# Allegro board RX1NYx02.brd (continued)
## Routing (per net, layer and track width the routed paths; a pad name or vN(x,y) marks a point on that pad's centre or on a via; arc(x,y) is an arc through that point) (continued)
GND_BD1: length 1822.2
  TOP w0.102: v1(91.38,-57.26) 91.39,-57.27 U26.3
  TOP w0.254: C16.2 v1(93.7,-62.06) ; U24.9 v1(94.4,-67.31) ; C2.1 v1(90.66,-49.41) ; C4.1 82.16,-40.92 v1(82.39,-41.15) ; C1.2 v1(108.7,-32.26) ; C3.1 82.16,-44.1 v1(82.39,-44.33) ; C5.1 82.16,-52.1 v1(82.39,-52.33) ; C9.1 82.16,-47.27 v1(82.39,-47.5) ; C166.2 v1(94,-58.86) ; C8.1 v1(90.66,-43.06)
  TOP w0.381: v1(1.94,-42.11) v1(3.43,-42.11) ; v1(89.65,-39.63) 90.22,-39.63 90.6,-40.01 U6.3 ; v1(1.94,-32.7) v1(3.43,-32.7) ; v1(1.94,-36.3) v1(3.43,-36.3) ; P_OCP1.A46 v1(3.43,-56.62) ; v1(3.43,-62.02) P_OCP1.A55 ; P_OCP1.A52 v1(3.43,-60.22) ; v1(1.94,-47.51) v1(3.43,-47.51) ; v1(1.94,-15.1) v1(3.43,-15.1) ; U5.3 v1(87.11,-50.41) ; v1(1.94,-38.1) v1(3.43,-38.1) ; v1(91.3,-45.85) 91.3,-46.6 90.92,-46.98 U1.3 ; P_OCP1.A49 v1(3.43,-58.42) ; v1(1.94,-29.1) v1(3.43,-29.1) ; U3.3 v1(87.11,-39.23) ; v1(1.94,-30.9) v1(3.43,-30.9) ; v1(1.94,-43.91) v1(3.43,-43.91) ; U7.3 v1(87.11,-45.58) ; P_OCP1.A43 v1(3.43,-54.82) ; P_OCP1.A64 v1(3.43,-67.42) ; U4.1 v1(98.92,-32.26) ; v1(1.94,-16.9) v1(3.43,-16.9) ; P_OCP1.A58 v1(3.43,-63.82) ; U2.3 v1(87.11,-42.41) ; v1(1.94,-49.31) v1(3.43,-49.31) ; P_OCP1.A61 v1(3.43,-65.62) ; v1(1.94,-34.5) v1(3.43,-34.5) ; P_OCP1.A67 v1(3.43,-69.22) ; v1(1.94,-45.71) v1(3.43,-45.71)
  TOP w0.508: C163.1 96.17,-29.64 v1(96.89,-30.36) ; v1(104.51,-30.61) 104.44,-30.54 Q1.2 ; SW1.2 v1(91.55,-44.45) ; C148.1 v1(88.81,-63.63) ; DS_BD1_PWR.2 v1(105.65,-15.24) ; C149.1 v1(88.81,-68.2)
  GND w0.254: 19.35,-50.36 P_CPU_OCP_3_P.3 ; P_CPU_OCP_3_P.3 20.48,-50.36 ; P_CPU_OCP_3_P.3 20.48,-51.48 ; P_CPU_OCP_3_P.3 19.35,-51.48 ; 15.05,-11.86 P_BD1_CLK2_N.3 ; P_BD1_CLK2_N.3 15.05,-10.73 ; P_BD1_CLK2_N.3 16.18,-10.73 ; P_BD1_CLK2_N.3 16.18,-11.86 ; P_OCP_CPU_1_P.4 100.49,-23.29 ; P_OCP_CPU_1_P.4 99.36,-23.29 ; P_OCP_CPU_1_P.4 99.36,-22.16 ; P_OCP_CPU_1_P.4 100.49,-22.16 ; 60.77,-7.56 P_BD1_CLK3_N.4 ; P_BD1_CLK3_N.4 61.9,-6.43 ; P_BD1_CLK3_N.4 60.77,-6.43 ; P_BD1_CLK3_N.4 61.9,-7.56 ; 65.07,-74.34 P_OCP_CPU_6_P.3 ; P_OCP_CPU_6_P.3 66.2,-73.22 ; P_OCP_CPU_6_P.3 65.07,-73.22 ; P_OCP_CPU_6_P.3 66.2,-74.34 ; 83.58,-36.8 P1.2 ; P1.2 85.05,-36.8 ; P1.2 83.58,-35.34 ; P1.2 85.05,-35.34 ; P_OCP_CPU_1_P.5 97.14,-23.29 ; P_OCP_CPU_1_P.5 96.01,-23.29 ; P_OCP_CPU_1_P.5 97.14,-22.16 ; P_OCP_CPU_1_P.5 96.01,-22.16 ; 65.07,-34.63 P_OCP_CPU_3_N.4 ; P_OCP_CPU_3_N.4 66.2,-34.63 ; P_OCP_CPU_3_N.4 66.2,-35.75 ; P_OCP_CPU_3_N.4 65.07,-35.75 ; P_CPU_OCP_0_P.3 31.91,-23.2 ; P_CPU_OCP_0_P.3 30.78,-24.32 ; P_CPU_OCP_0_P.3 31.91,-24.32 ; P_CPU_OCP_0_P.3 30.78,-23.2 ; 27.43,-23.2 P_CPU_OCP_0_P.2 ; P_CPU_OCP_0_P.2 28.56,-24.32 ; P_CPU_OCP_0_P.2 27.43,-24.32 ; P_CPU_OCP_0_P.2 28.56,-23.2 ; 18.4,-28.62 P_CPU_OCP_0_N.2 ; P_CPU_OCP_0_N.2 19.53,-28.62 ; P_CPU_OCP_0_N.2 19.53,-27.5 ; P_CPU_OCP_0_N.2 18.4,-27.5 ; 65.07,-70.99 P_OCP_CPU_6_P.2 ; P_OCP_CPU_6_P.2 65.07,-69.87 ; P_OCP_CPU_6_P.2 66.2,-69.87 ; P_OCP_CPU_6_P.2 66.2,-70.99 ; P_OCP_CPU_4_N.3 50.47,-35.75 ; P_OCP_CPU_4_N.3 49.34,-35.75 ; P_OCP_CPU_4_N.3 50.47,-34.63 ; P_OCP_CPU_4_N.3 49.34,-34.63 ; 60.77,-37.98 P_OCP_CPU_3_N.2 ; P_OCP_CPU_3_N.2 61.9,-39.1 ; P_OCP_CPU_3_N.2 61.9,-37.98 ; P_OCP_CPU_3_N.2 60.77,-39.1 ; 64.12,-23.2 P_OCP_CPU_0_P.5 ; P_OCP_CPU_0_P.5 65.25,-24.32 ; P_OCP_CPU_0_P.5 65.25,-23.2 ; P_OCP_CPU_0_P.5 64.12,-24.32 ; 30.78,-51.48 P_CPU_OCP_2_P.3 ; P_CPU_OCP_2_P.3 31.91,-50.36 ; P_CPU_OCP_2_P.3 30.78,-50.36 ; P_CPU_OCP_2_P.3 31.91,-51.48 ; P_BD1_CLK1_P.2 97.14,-6.43 ; P_BD1_CLK1_P.2 96.01,-6.43 ; P_BD1_CLK1_P.2 97.14,-7.56 ; P_BD1_CLK1_P.2 96.01,-7.56 ; P_BD1_CLK0_P.2 51.42,-7.56 ; P_BD1_CLK0_P.2 50.29,-7.56 ; P_BD1_CLK0_P.2 50.29,-6.43 ; P_BD1_CLK0_P.2 51.42,-6.43 ; 60.77,-34.63 P_OCP_CPU_3_N.3 ; P_OCP_CPU_3_N.3 60.77,-35.75 ; P_OCP_CPU_3_N.3 61.9,-35.75 ; P_OCP_CPU_3_N.3 61.9,-34.63 ; P_OCP_CPU_2_P.4 73.33,-51.48 ; P_OCP_CPU_2_P.4 72.2,-50.36 ; P_OCP_CPU_2_P.4 72.2,-51.48 ; P_OCP_CPU_2_P.4 73.33,-50.36 ; P_CPU_OCP_7_N.5 20.48,-60.84 ; P_CPU_OCP_7_N.5 19.35,-60.84 ; P_CPU_OCP_7_N.5 20.48,-61.96 ; P_CPU_OCP_7_N.5 19.35,-61.96 ; 76.5,-51.48 P_OCP_CPU_2_P.3 ; P_OCP_CPU_2_P.3 76.5,-50.36 ; P_OCP_CPU_2_P.3 77.63,-50.36 ; P_OCP_CPU_2_P.3 77.63,-51.48 ; P_BD1_CMTS_N.3 97.46,-58.61 ; P_BD1_CMTS_N.3 96.33,-58.61 ; P_BD1_CMTS_N.3 97.46,-57.49 ; P_BD1_CMTS_N.3 96.33,-57.49 ; P_BD1_CLK0_N.2 42.39,-10.73 ; P_BD1_CLK0_N.2 42.39,-11.86 ; P_BD1_CLK0_N.2 41.26,-11.86 ; P_BD1_CLK0_N.2 41.26,-10.73 ; 15.05,-35.75 P_CPU_OCP_3_N.3 ; P_CPU_OCP_3_N.3 16.18,-34.63 ; P_CPU_OCP_3_N.3 15.05,-34.63 ; P_CPU_OCP_3_N.3 16.18,-35.75 ; P_CPU_OCP_1_N.2 42.39,-27.5 ; P_CPU_OCP_1_N.2 41.26,-28.62 ; P_CPU_OCP_1_N.2 42.39,-28.62 ; P_CPU_OCP_1_N.2 41.26,-27.5 ; 42.21,-73.22 P_CPU_OCP_5_P.3 ; P_CPU_OCP_5_P.3 42.21,-74.34 ; P_CPU_OCP_5_P.3 43.34,-74.34 ; P_CPU_OCP_5_P.3 43.34,-73.22 ; 37.91,-74.34 P_CPU_OCP_5_P.4 ; P_CPU_OCP_5_P.4 37.91,-73.22 ; P_CPU_OCP_5_P.4 39.04,-73.22 ; P_CPU_OCP_5_P.4 39.04,-74.34 ; P_CPU_OCP_6_P.2 31.91,-69.87 ; P_CPU_OCP_6_P.2 30.78,-69.87 ; P_CPU_OCP_6_P.2 31.91,-70.99 ; P_CPU_OCP_6_P.2 30.78,-70.99 ; 83.63,-60.84 P_BD1_TRIG_IN_P.2 ; P_BD1_TRIG_IN_P.2 84.76,-60.84 ; P_BD1_TRIG_IN_P.2 83.63,-61.96 ; P_BD1_TRIG_IN_P.2 84.76,-61.96 ; 49.34,-47.01 P_OCP_CPU_4_P.5 ; P_OCP_CPU_4_P.5 50.47,-47.01 ; P_OCP_CPU_4_P.5 49.34,-48.13 ; P_OCP_CPU_4_P.5 50.47,-48.13 ; 18.4,-10.73 P_BD1_CLK2_N.2 ; P_BD1_CLK2_N.2 18.4,-11.86 ; P_BD1_CLK2_N.2 19.53,-10.73 ; P_BD1_CLK2_N.2 19.53,-11.86 ; P_OCP_CPU_2_P.5 73.33,-47.01 ; P_OCP_CPU_2_P.5 72.2,-47.01 ; P_OCP_CPU_2_P.5 72.2,-48.13 ; P_OCP_CPU_2_P.5 73.33,-48.13 ; P_CPU_OCP_7_P.2 20.48,-69.87 ; P_CPU_OCP_7_P.2 20.48,-70.99 ; P_CPU_OCP_7_P.2 19.35,-70.99 ; P_CPU_OCP_7_P.2 19.35,-69.87 ; P_BD1_CMTS_P.5 97.46,-70.99 ; P_BD1_CMTS_P.5 97.46,-69.87 ; P_BD1_CMTS_P.5 96.33,-69.87 ; P_BD1_CMTS_P.5 96.33,-70.99 ; 87.93,-74.34 P_BD1_TRIG_IN_N.3 ; P_BD1_TRIG_IN_N.3 89.06,-74.34 ; P_BD1_TRIG_IN_N.3 87.93,-73.22 ; P_BD1_TRIG_IN_N.3 89.06,-73.22 ; P_BD1_TRIG_IN_N.5 84.76,-69.87 ; P_BD1_TRIG_IN_N.5 84.76,-70.99 ; P_BD1_TRIG_IN_N.5 83.63,-69.87 ; P_BD1_TRIG_IN_N.5 83.63,-70.99 ; 76.5,-6.43 P_BD1_CLK3_P.3 ; P_BD1_CLK3_P.3 77.63,-6.43 ; P_BD1_CLK3_P.3 76.5,-7.56 ; P_BD1_CLK3_P.3 77.63,-7.56 ; 30.78,-57.49 P_CPU_OCP_6_N.4 ; P_CPU_OCP_6_N.4 31.91,-58.61 ; P_CPU_OCP_6_N.4 30.78,-58.61 ; P_CPU_OCP_6_N.4 31.91,-57.49 ; 53.64,-69.87 P_OCP_CPU_7_P.2 ; P_OCP_CPU_7_P.2 54.77,-70.99 ; P_OCP_CPU_7_P.2 54.77,-69.87 ; P_OCP_CPU_7_P.2 53.64,-70.99 ; P_BD1_TRIG_IN_P.5 89.06,-60.84 ; P_BD1_TRIG_IN_P.5 89.06,-61.96 ; P_BD1_TRIG_IN_P.5 87.93,-60.84 ; P_BD1_TRIG_IN_P.5 87.93,-61.96 ; P_OCP_CPU_7_N.2 50.47,-61.96 ; P_OCP_CPU_7_N.2 49.34,-60.84 ; P_OCP_CPU_7_N.2 50.47,-60.84 ; P_OCP_CPU_7_N.2 49.34,-61.96 ; 64.12,-10.73 P_BD1_CLK3_N.2 ; P_BD1_CLK3_N.2 65.25,-11.86 ; P_BD1_CLK3_N.2 65.25,-10.73 ; P_BD1_CLK3_N.2 64.12,-11.86 ; 15.05,-39.1 P_CPU_OCP_3_N.2 ; P_CPU_OCP_3_N.2 15.05,-37.98 ; P_CPU_OCP_3_N.2 16.18,-39.1 ; P_CPU_OCP_3_N.2 16.18,-37.98 ; P_OCP_CPU_6_N.4 66.2,-57.49 ; P_OCP_CPU_6_N.4 66.2,-58.61 ; P_OCP_CPU_6_N.4 65.07,-58.61 ; P_OCP_CPU_6_N.4 65.07,-57.49 ; 53.64,-57.49 P_OCP_CPU_7_N.4 ; P_OCP_CPU_7_N.4 53.64,-58.61 ; P_OCP_CPU_7_N.4 54.77,-57.49 ; P_OCP_CPU_7_N.4 54.77,-58.61 ; 30.78,-28.62 P_CPU_OCP_0_P.4 ; P_CPU_OCP_0_P.4 31.91,-27.5 ; P_CPU_OCP_0_P.4 31.91,-28.62 ; P_CPU_OCP_0_P.4 30.78,-27.5 ; 60.77,-69.87 P_OCP_CPU_6_P.5 ; P_OCP_CPU_6_P.5 61.9,-69.87 ; P_OCP_CPU_6_P.5 61.9,-70.99 ; P_OCP_CPU_6_P.5 60.77,-70.99 ; P2.2 89.49,-36.8 ; P2.2 88.02,-36.8 ; P2.2 88.02,-35.34 ; P2.2 89.49,-35.34 ; P_BD1_CMTS_N.4 101.76,-57.49 ; P_BD1_CMTS_N.4 101.76,-58.61 ; P_BD1_CMTS_N.4 100.63,-58.61 ; P_BD1_CMTS_N.4 100.63,-57.49 ; 60.77,-11.86 P_BD1_CLK3_N.3 ; P_BD1_CLK3_N.3 61.9,-11.86 ; P_BD1_CLK3_N.3 60.77,-10.73 ; P_BD1_CLK3_N.3 61.9,-10.73 ; P_OCP_CPU_3_P.2 66.2,-47.01 ; P_OCP_CPU_3_P.2 66.2,-48.13 ; P_OCP_CPU_3_P.2 65.07,-48.13 ; P_OCP_CPU_3_P.2 65.07,-47.01 ; P_OCP_CPU_3_N.5 66.2,-39.1 ; P_OCP_CPU_3_N.5 65.07,-39.1 ; P_OCP_CPU_3_N.5 65.07,-37.98 ; P_OCP_CPU_3_N.5 66.2,-37.98 ; 27.43,-27.5 P_CPU_OCP_0_P.5 ; P_CPU_OCP_0_P.5 28.56,-27.5 ; P_CPU_OCP_0_P.5 27.43,-28.62 ; P_CPU_OCP_0_P.5 28.56,-28.62 ; 96.33,-74.34 P_BD1_CMTS_P.4 ; P_BD1_CMTS_P.4 97.46,-74.34 ; P_BD1_CMTS_P.4 97.46,-73.22 ; P_BD1_CMTS_P.4 96.33,-73.22 ; P_BD1_TRIG_IN_N.2 89.06,-70.99 ; P_BD1_TRIG_IN_N.2 89.06,-69.87 ; P_BD1_TRIG_IN_N.2 87.93,-70.99 ; P_BD1_TRIG_IN_N.2 87.93,-69.87 ; 86.98,-23.29 P_OCP_CPU_1_N.2 ; P_OCP_CPU_1_N.2 88.11,-23.29 ; P_OCP_CPU_1_N.2 86.98,-22.16 ; P_OCP_CPU_1_N.2 88.11,-22.16 ; 83.63,-57.49 P_BD1_TRIG_IN_P.3 ; P_BD1_TRIG_IN_P.3 83.63,-58.61 ; P_BD1_TRIG_IN_P.3 84.76,-58.61 ; P_BD1_TRIG_IN_P.3 84.76,-57.49 ; 100.63,-74.34 P_BD1_CMTS_P.3 ; P_BD1_CMTS_P.3 101.76,-73.22 ; P_BD1_CMTS_P.3 100.63,-73.22 ; P_BD1_CMTS_P.3 101.76,-74.34 ; 26.48,-48.13 P_CPU_OCP_2_P.5 ; P_CPU_OCP_2_P.5 27.61,-47.01 ; P_CPU_OCP_2_P.5 26.48,-47.01 ; P_CPU_OCP_2_P.5 27.61,-48.13 ; 41.26,-7.56 P_BD1_CLK0_N.5 ; P_BD1_CLK0_N.5 42.39,-6.43 ; P_BD1_CLK0_N.5 42.39,-7.56 ; P_BD1_CLK0_N.5 41.26,-6.43 ; P_BD1_CLK3_P.4 77.63,-10.73 ; P_BD1_CLK3_P.4 76.5,-10.73 ; P_BD1_CLK3_P.4 77.63,-11.86 ; P_BD1_CLK3_P.4 76.5,-11.86 ; 92.6,-29.69 P13.2 ; P13.2 94.06,-29.69 ; P13.2 92.6,-28.23 ; P13.2 94.06,-28.23 ; 37.91,-57.49 P_CPU_OCP_5_N.3 ; P_CPU_OCP_5_N.3 39.04,-58.61 ; P_CPU_OCP_5_N.3 39.04,-57.49 ; P_CPU_OCP_5_N.3 37.91,-58.61 ; 15.05,-70.99 P_CPU_OCP_7_P.5 ; P_CPU_OCP_7_P.5 16.18,-69.87 ; P_CPU_OCP_7_P.5 16.18,-70.99 ; P_CPU_OCP_7_P.5 15.05,-69.87 ; 65.07,-50.36 P_OCP_CPU_3_P.3 ; P_OCP_CPU_3_P.3 66.2,-51.48 ; P_OCP_CPU_3_P.3 65.07,-51.48 ; P_OCP_CPU_3_P.3 66.2,-50.36 ; 30.78,-37.98 P_CPU_OCP_2_N.5 ; P_CPU_OCP_2_N.5 31.91,-37.98 ; P_CPU_OCP_2_N.5 30.78,-39.1 ; P_CPU_OCP_2_N.5 31.91,-39.1 ; 60.77,-58.61 P_OCP_CPU_6_N.3 ; P_OCP_CPU_6_N.3 60.77,-57.49 ; P_OCP_CPU_6_N.3 61.9,-57.49 ; P_OCP_CPU_6_N.3 61.9,-58.61 ; 49.34,-74.34 P_OCP_CPU_7_P.4 ; P_OCP_CPU_7_P.4 50.47,-74.34 ; P_OCP_CPU_7_P.4 49.34,-73.22 ; P_OCP_CPU_7_P.4 50.47,-73.22 ; 99.36,-17.86 P_OCP_CPU_1_P.3 ; P_OCP_CPU_1_P.3 99.36,-18.99 ; P_OCP_CPU_1_P.3 100.49,-17.86 ; P_OCP_CPU_1_P.3 100.49,-18.99 ; P_OCP_CPU_0_P.2 65.25,-27.5 ; P_OCP_CPU_0_P.2 65.25,-28.62 ; P_OCP_CPU_0_P.2 64.12,-28.62 ; P_OCP_CPU_0_P.2 64.12,-27.5 ; P_BD1_CMTS_N.5 101.76,-61.96 ; P_BD1_CMTS_N.5 101.76,-60.84 ; P_BD1_CMTS_N.5 100.63,-61.96 ; P_BD1_CMTS_N.5 100.63,-60.84 ; 42.21,-57.49 P_CPU_OCP_5_N.4 ; P_CPU_OCP_5_N.4 43.34,-57.49 ; P_CPU_OCP_5_N.4 43.34,-58.61 ; P_CPU_OCP_5_N.4 42.21,-58.61 ; P_BD1_CLK1_N.5 88.11,-6.43 ; P_BD1_CLK1_N.5 86.98,-6.43 ; P_BD1_CLK1_N.5 86.98,-7.56 ; P_BD1_CLK1_N.5 88.11,-7.56 ; 53.64,-47.01 P_OCP_CPU_4_P.2 ; P_OCP_CPU_4_P.2 54.77,-47.01 ; P_OCP_CPU_4_P.2 53.64,-48.13 ; P_OCP_CPU_4_P.2 54.77,-48.13 ; 76.5,-24.32 P_OCP_CPU_0_N.3 ; P_OCP_CPU_0_N.3 76.5,-23.2 ; P_OCP_CPU_0_N.3 77.63,-23.2 ; P_OCP_CPU_0_N.3 77.63,-24.32 ; P_OCP_CPU_3_P.5 61.9,-47.01 ; P_OCP_CPU_3_P.5 60.77,-48.13 ; P_OCP_CPU_3_P.5 60.77,-47.01 ; P_OCP_CPU_3_P.5 61.9,-48.13 ; P_CPU_OCP_4_P.2 43.34,-47.01 ; P_CPU_OCP_4_P.2 42.21,-47.01 ; P_CPU_OCP_4_P.2 42.21,-48.13 ; P_CPU_OCP_4_P.2 43.34,-48.13 ; P_BD1_CLK2_N.4 16.18,-7.56 ; P_BD1_CLK2_N.4 15.05,-7.56 ; P_BD1_CLK2_N.4 15.05,-6.43 ; P_BD1_CLK2_N.4 16.18,-6.43 ; P_CPU_OCP_1_P.5 51.42,-27.5 ; P_CPU_OCP_1_P.5 51.42,-28.62 ; P_CPU_OCP_1_P.5 50.29,-27.5 ; P_CPU_OCP_1_P.5 50.29,-28.62 ; 30.78,-73.22 P_CPU_OCP_6_P.3 ; P_CPU_OCP_6_P.3 31.91,-73.22 ; P_CPU_OCP_6_P.3 31.91,-74.34 ; P_CPU_OCP_6_P.3 30.78,-74.34 ; P3.2 93.94,-35.34 ; P3.2 92.47,-35.34 ; P3.2 93.94,-36.8 ; P3.2 92.47,-36.8 ; P_CPU_OCP_4_P.4 39.04,-51.48 ; P_CPU_OCP_4_P.4 39.04,-50.36 ; P_CPU_OCP_4_P.4 37.91,-50.36 ; P_CPU_OCP_4_P.4 37.91,-51.48 ; P_CPU_OCP_6_P.4 27.61,-73.22 ; P_CPU_OCP_6_P.4 26.48,-74.34 ; P_CPU_OCP_6_P.4 26.48,-73.22 ; P_CPU_OCP_6_P.4 27.61,-74.34 ; P_CPU_OCP_5_P.2 43.34,-70.99 ; P_CPU_OCP_5_P.2 43.34,-69.87 ; P_CPU_OCP_5_P.2 42.21,-70.99 ; P_CPU_OCP_5_P.2 42.21,-69.87 ; 37.91,-11.86 P_BD1_CLK0_N.3 ; P_BD1_CLK0_N.3 39.04,-11.86 ; P_BD1_CLK0_N.3 37.91,-10.73 ; P_BD1_CLK0_N.3 39.04,-10.73 ; 53.64,-10.73 P_BD1_CLK0_P.4 ; P_BD1_CLK0_P.4 54.77,-11.86 ; P_BD1_CLK0_P.4 53.64,-11.86 ; P_BD1_CLK0_P.4 54.77,-10.73 ; 72.2,-70.99 P_OCP_CPU_5_P.5 ; P_OCP_CPU_5_P.5 73.33,-70.99 ; P_OCP_CPU_5_P.5 73.33,-69.87 ; P_OCP_CPU_5_P.5 72.2,-69.87 ; 73.15,-7.56 P_BD1_CLK3_P.2 ; P_BD1_CLK3_P.2 73.15,-6.43 ; P_BD1_CLK3_P.2 74.28,-6.43 ; P_BD1_CLK3_P.2 74.28,-7.56 ; P_OCP_CPU_1_P.2 97.14,-18.99 ; P_OCP_CPU_1_P.2 96.01,-18.99 ; P_OCP_CPU_1_P.2 96.01,-17.86 ; P_OCP_CPU_1_P.2 97.14,-17.86 ; P_OCP_CPU_4_P.3 54.77,-50.36 ; P_OCP_CPU_4_P.3 53.64,-51.48 ; P_OCP_CPU_4_P.3 54.77,-51.48 ; P_OCP_CPU_4_P.3 53.64,-50.36 ; 49.34,-50.36 P_OCP_CPU_4_P.4 ; P_OCP_CPU_4_P.4 50.47,-50.36 ; P_OCP_CPU_4_P.4 50.47,-51.48 ; P_OCP_CPU_4_P.4 49.34,-51.48 ; 87.93,-58.61 P_BD1_TRIG_IN_P.4 ; P_BD1_TRIG_IN_P.4 89.06,-58.61 ; P_BD1_TRIG_IN_P.4 89.06,-57.49 ; P_BD1_TRIG_IN_P.4 87.93,-57.49 ; 37.91,-7.56 P_BD1_CLK0_N.4 ; P_BD1_CLK0_N.4 39.04,-6.43 ; P_BD1_CLK0_N.4 37.91,-6.43 ; P_BD1_CLK0_N.4 39.04,-7.56 ; P_BD1_CLK0_P.5 51.42,-11.86 ; P_BD1_CLK0_P.5 51.42,-10.73 ; P_BD1_CLK0_P.5 50.29,-11.86 ; P_BD1_CLK0_P.5 50.29,-10.73 ; P_OCP_CPU_2_N.3 73.33,-34.63 ; P_OCP_CPU_2_N.3 73.33,-35.75 ; P_OCP_CPU_2_N.3 72.2,-35.75 ; P_OCP_CPU_2_N.3 72.2,-34.63 ; P_BD1_CMTS_P.2 101.76,-69.87 ; P_BD1_CMTS_P.2 101.76,-70.99 ; P_BD1_CMTS_P.2 100.63,-70.99 ; P_BD1_CMTS_P.2 100.63,-69.87 ; P_CPU_OCP_4_P.5 39.04,-48.13 ; P_CPU_OCP_4_P.5 37.91,-48.13 ; P_CPU_OCP_4_P.5 39.04,-47.01 ; P_CPU_OCP_4_P.5 37.91,-47.01 ; 72.2,-39.1 P_OCP_CPU_2_N.2 ; P_OCP_CPU_2_N.2 73.33,-39.1 ; P_OCP_CPU_2_N.2 72.2,-37.98 ; P_OCP_CPU_2_N.2 73.33,-37.98 ; 42.21,-35.75 P_CPU_OCP_4_N.4 ; P_CPU_OCP_4_N.4 43.34,-34.63 ; P_CPU_OCP_4_N.4 42.21,-34.63 ; P_CPU_OCP_4_N.4 43.34,-35.75 ; P_CPU_OCP_0_N.5 19.53,-24.32 ; P_CPU_OCP_0_N.5 19.53,-23.2 ; P_CPU_OCP_0_N.5 18.4,-23.2 ; P_CPU_OCP_0_N.5 18.4,-24.32 ; 76.5,-60.84 P_OCP_CPU_5_N.5 ; P_OCP_CPU_5_N.5 77.63,-60.84 ; P_OCP_CPU_5_N.5 77.63,-61.96 ; P_OCP_CPU_5_N.5 76.5,-61.96 ; 37.91,-24.32 P_CPU_OCP_1_N.4 ; P_CPU_OCP_1_N.4 37.91,-23.2 ; P_CPU_OCP_1_N.4 39.04,-24.32 ; P_CPU_OCP_1_N.4 39.04,-23.2 ; 53.64,-24.32 P_CPU_OCP_1_P.3 ; P_CPU_OCP_1_P.3 54.77,-24.32 ; P_CPU_OCP_1_P.3 53.64,-23.2 ; P_CPU_OCP_1_P.3 54.77,-23.2 ; 37.91,-69.87 P_CPU_OCP_5_P.5 ; P_CPU_OCP_5_P.5 39.04,-70.99 ; P_CPU_OCP_5_P.5 39.04,-69.87 ; P_CPU_OCP_5_P.5 37.91,-70.99 ; P_CPU_OCP_6_P.5 27.61,-70.99 ; P_CPU_OCP_6_P.5 26.48,-70.99 ; P_CPU_OCP_6_P.5 26.48,-69.87 ; P_CPU_OCP_6_P.5 27.61,-69.87 ; 27.43,-10.73 P_BD1_CLK2_P.5 ; P_BD1_CLK2_P.5 28.56,-11.86 ; P_BD1_CLK2_P.5 28.56,-10.73 ; P_BD1_CLK2_P.5 27.43,-11.86 ; P_OCP_CPU_2_P.2 77.63,-47.01 ; P_OCP_CPU_2_P.2 76.5,-48.13 ; P_OCP_CPU_2_P.2 76.5,-47.01 ; P_OCP_CPU_2_P.2 77.63,-48.13 ; 19.35,-57.49 P_CPU_OCP_7_N.4 ; P_CPU_OCP_7_N.4 20.48,-58.61 ; P_CPU_OCP_7_N.4 19.35,-58.61 ; P_CPU_OCP_7_N.4 20.48,-57.49 ; 99.36,-11.86 P_BD1_CLK1_P.4 ; P_BD1_CLK1_P.4 100.49,-10.73 ; P_BD1_CLK1_P.4 99.36,-10.73 ; P_BD1_CLK1_P.4 100.49,-11.86 ; 26.48,-35.75 P_CPU_OCP_2_N.3 ; P_CPU_OCP_2_N.3 27.61,-35.75 ; P_CPU_OCP_2_N.3 26.48,-34.63 ; P_CPU_OCP_2_N.3 27.61,-34.63 ; 76.5,-57.49 P_OCP_CPU_5_N.4 ; P_OCP_CPU_5_N.4 77.63,-57.49 ; P_OCP_CPU_5_N.4 77.63,-58.61 ; P_OCP_CPU_5_N.4 76.5,-58.61 ; 30.78,-60.84 P_CPU_OCP_6_N.5 ; P_CPU_OCP_6_N.5 31.91,-60.84 ; P_CPU_OCP_6_N.5 31.91,-61.96 ; P_CPU_OCP_6_N.5 30.78,-61.96 ; 37.91,-28.62 P_CPU_OCP_1_N.3 ; P_CPU_OCP_1_N.3 37.91,-27.5 ; P_CPU_OCP_1_N.3 39.04,-28.62 ; P_CPU_OCP_1_N.3 39.04,-27.5 ; 19.35,-47.01 P_CPU_OCP_3_P.2 ; P_CPU_OCP_3_P.2 19.35,-48.13 ; P_CPU_OCP_3_P.2 20.48,-48.13 ; P_CPU_OCP_3_P.2 20.48,-47.01 ; 19.35,-39.1 P_CPU_OCP_3_N.5 ; P_CPU_OCP_3_N.5 20.48,-39.1 ; P_CPU_OCP_3_N.5 20.48,-37.98 ; P_CPU_OCP_3_N.5 19.35,-37.98 ; P_OCP_CPU_1_N.5 88.11,-18.99 ; P_OCP_CPU_1_N.5 88.11,-17.86 ; P_OCP_CPU_1_N.5 86.98,-18.99 ; P_OCP_CPU_1_N.5 86.98,-17.86 ; P_OCP_CPU_6_N.5 66.2,-60.84 ; P_OCP_CPU_6_N.5 65.07,-60.84 ; P_OCP_CPU_6_N.5 66.2,-61.96 ; P_OCP_CPU_6_N.5 65.07,-61.96 ; 76.5,-73.22 P_OCP_CPU_5_P.3 ; P_OCP_CPU_5_P.3 76.5,-74.34 ; P_OCP_CPU_5_P.3 77.63,-73.22 ; P_OCP_CPU_5_P.3 77.63,-74.34 ; P_BD1_CLK1_N.3 84.76,-11.86 ; P_BD1_CLK1_N.3 83.63,-11.86 ; P_BD1_CLK1_N.3 83.63,-10.73 ; P_BD1_CLK1_N.3 84.76,-10.73 ; 49.34,-39.1 P_OCP_CPU_4_N.2 ; P_OCP_CPU_4_N.2 49.34,-37.98 ; P_OCP_CPU_4_N.2 50.47,-37.98 ; P_OCP_CPU_4_N.2 50.47,-39.1 ; P_OCP_CPU_0_N.5 74.28,-27.5 ; P_OCP_CPU_0_N.5 73.15,-28.62 ; P_OCP_CPU_0_N.5 73.15,-27.5 ; P_OCP_CPU_0_N.5 74.28,-28.62 ; 26.48,-60.84 P_CPU_OCP_6_N.2 ; P_CPU_OCP_6_N.2 27.61,-60.84 ; P_CPU_OCP_6_N.2 27.61,-61.96 ; P_CPU_OCP_6_N.2 26.48,-61.96 ; P_OCP_CPU_7_N.5 54.77,-60.84 ; P_OCP_CPU_7_N.5 54.77,-61.96 ; P_OCP_CPU_7_N.5 53.64,-61.96 ; P_OCP_CPU_7_N.5 53.64,-60.84 ; P_BD1_CLK2_P.2 28.56,-6.43 ; P_BD1_CLK2_P.2 27.43,-7.56 ; P_BD1_CLK2_P.2 28.56,-7.56 ; P_BD1_CLK2_P.2 27.43,-6.43 ; 76.5,-70.99 P_OCP_CPU_5_P.2 ; P_OCP_CPU_5_P.2 77.63,-70.99 ; P_OCP_CPU_5_P.2 77.63,-69.87 ; P_OCP_CPU_5_P.2 76.5,-69.87 ; P_OCP_CPU_7_P.5 50.47,-70.99 ; P_OCP_CPU_7_P.5 50.47,-69.87 ; P_OCP_CPU_7_P.5 49.34,-69.87 ; P_OCP_CPU_7_P.5 49.34,-70.99 ; 26.48,-39.1 P_CPU_OCP_2_N.2 ; P_CPU_OCP_2_N.2 27.61,-37.98 ; P_CPU_OCP_2_N.2 26.48,-37.98 ; P_CPU_OCP_2_N.2 27.61,-39.1 ; 41.26,-23.2 P_CPU_OCP_1_N.5 ; P_CPU_OCP_1_N.5 41.26,-24.32 ; P_CPU_OCP_1_N.5 42.39,-23.2 ; P_CPU_OCP_1_N.5 42.39,-24.32 ; P_CPU_OCP_3_N.4 20.48,-35.75 ; P_CPU_OCP_3_N.4 19.35,-35.75 ; P_CPU_OCP_3_N.4 20.48,-34.63 ; P_CPU_OCP_3_N.4 19.35,-34.63 ; 26.48,-51.48 P_CPU_OCP_2_P.4 ; P_CPU_OCP_2_P.4 27.61,-51.48 ; P_CPU_OCP_2_P.4 26.48,-50.36 ; P_CPU_OCP_2_P.4 27.61,-50.36 ; P_OCP_CPU_7_P.3 54.77,-73.22 ; P_OCP_CPU_7_P.3 54.77,-74.34 ; P_OCP_CPU_7_P.3 53.64,-74.34 ; P_OCP_CPU_7_P.3 53.64,-73.22 ; P_CPU_OCP_1_P.2 51.42,-24.32 ; P_CPU_OCP_1_P.2 51.42,-23.2 ; P_CPU_OCP_1_P.2 50.29,-23.2 ; P_CPU_OCP_1_P.2 50.29,-24.32 ; P_OCP_CPU_5_N.2 73.33,-60.84 ; P_OCP_CPU_5_N.2 72.2,-61.96 ; P_OCP_CPU_5_N.2 73.33,-61.96 ; P_OCP_CPU_5_N.2 72.2,-60.84 ; P_OCP_CPU_1_N.4 84.76,-17.86 ; P_OCP_CPU_1_N.4 83.63,-18.99 ; P_OCP_CPU_1_N.4 83.63,-17.86 ; P_OCP_CPU_1_N.4 84.76,-18.99 ; 60.77,-24.32 P_OCP_CPU_0_P.4 ; P_OCP_CPU_0_P.4 61.9,-24.32 ; P_OCP_CPU_0_P.4 60.77,-23.2 ; P_OCP_CPU_0_P.4 61.9,-23.2 ; 15.05,-60.84 P_CPU_OCP_7_N.2 ; P_CPU_OCP_7_N.2 16.18,-60.84 ; P_CPU_OCP_7_N.2 15.05,-61.96 ; P_CPU_OCP_7_N.2 16.18,-61.96 ; 73.15,-11.86 P_BD1_CLK3_P.5 ; P_BD1_CLK3_P.5 73.15,-10.73 ; P_BD1_CLK3_P.5 74.28,-11.86 ; P_BD1_CLK3_P.5 74.28,-10.73 ; P_BD1_CLK3_N.5 65.25,-6.43 ; P_BD1_CLK3_N.5 64.12,-7.56 ; P_BD1_CLK3_N.5 64.12,-6.43 ; P_BD1_CLK3_N.5 65.25,-7.56 ; P_OCP_CPU_4_N.4 54.77,-34.63 ; P_OCP_CPU_4_N.4 53.64,-34.63 ; P_OCP_CPU_4_N.4 54.77,-35.75 ; P_OCP_CPU_4_N.4 53.64,-35.75 ; 53.64,-28.62 P_CPU_OCP_1_P.4 ; P_CPU_OCP_1_P.4 54.77,-27.5 ; P_CPU_OCP_1_P.4 53.64,-27.5 ; P_CPU_OCP_1_P.4 54.77,-28.62 ; P_CPU_OCP_7_N.3 16.18,-57.49 ; P_CPU_OCP_7_N.3 15.05,-58.61 ; P_CPU_OCP_7_N.3 15.05,-57.49 ; P_CPU_OCP_7_N.3 16.18,-58.61 ; P_OCP_CPU_7_N.3 50.47,-57.49 ; P_OCP_CPU_7_N.3 50.47,-58.61 ; P_OCP_CPU_7_N.3 49.34,-57.49 ; P_OCP_CPU_7_N.3 49.34,-58.61 ; P_CPU_OCP_5_N.2 39.04,-61.96 ; P_CPU_OCP_5_N.2 39.04,-60.84 ; P_CPU_OCP_5_N.2 37.91,-60.84 ; P_CPU_OCP_5_N.2 37.91,-61.96 ; P_CPU_OCP_7_P.4 16.18,-74.34 ; P_CPU_OCP_7_P.4 16.18,-73.22 ; P_CPU_OCP_7_P.4 15.05,-73.22 ; P_CPU_OCP_7_P.4 15.05,-74.34 ; P_CPU_OCP_4_P.3 43.34,-50.36 ; P_CPU_OCP_4_P.3 43.34,-51.48 ; P_CPU_OCP_4_P.3 42.21,-50.36 ; P_CPU_OCP_4_P.3 42.21,-51.48 ; 60.77,-73.22 P_OCP_CPU_6_P.4 ; P_OCP_CPU_6_P.4 61.9,-73.22 ; P_OCP_CPU_6_P.4 61.9,-74.34 ; P_OCP_CPU_6_P.4 60.77,-74.34 ; 83.63,-73.22 P_BD1_TRIG_IN_N.4 ; P_BD1_TRIG_IN_N.4 84.76,-74.34 ; P_BD1_TRIG_IN_N.4 83.63,-74.34 ; P_BD1_TRIG_IN_N.4 84.76,-73.22 ; P_OCP_CPU_6_N.2 61.9,-60.84 ; P_OCP_CPU_6_N.2 60.77,-61.96 ; P_OCP_CPU_6_N.2 61.9,-61.96 ; P_OCP_CPU_6_N.2 60.77,-60.84 ; 42.21,-61.96 P_CPU_OCP_5_N.5 ; P_CPU_OCP_5_N.5 43.34,-61.96 ; P_CPU_OCP_5_N.5 43.34,-60.84 ; P_CPU_OCP_5_N.5 42.21,-60.84 ; 15.05,-27.5 P_CPU_OCP_0_N.3 ; P_CPU_OCP_0_N.3 16.18,-27.5 ; P_CPU_OCP_0_N.3 16.18,-28.62 ; P_CPU_OCP_0_N.3 15.05,-28.62 ; 76.5,-37.98 P_OCP_CPU_2_N.5 ; P_OCP_CPU_2_N.5 77.63,-37.98 ; P_OCP_CPU_2_N.5 77.63,-39.1 ; P_OCP_CPU_2_N.5 76.5,-39.1 ; P_CPU_OCP_3_P.4 16.18,-51.48 ; P_CPU_OCP_3_P.4 16.18,-50.36 ; P_CPU_OCP_3_P.4 15.05,-50.36 ; P_CPU_OCP_3_P.4 15.05,-51.48 ; 72.2,-74.34 P_OCP_CPU_5_P.4 ; P_OCP_CPU_5_P.4 73.33,-73.22 ; P_OCP_CPU_5_P.4 72.2,-73.22 ; P_OCP_CPU_5_P.4 73.33,-74.34 ; 60.77,-51.48 P_OCP_CPU_3_P.4 ; P_OCP_CPU_3_P.4 61.9,-50.36 ; P_OCP_CPU_3_P.4 60.77,-50.36 ; P_OCP_CPU_3_P.4 61.9,-51.48 ; P_BD1_CMTS_N.2 97.46,-60.84 ; P_BD1_CMTS_N.2 96.33,-61.96 ; P_BD1_CMTS_N.2 97.46,-61.96 ; P_BD1_CMTS_N.2 96.33,-60.84 ; P_CPU_OCP_4_N.5 43.34,-39.1 ; P_CPU_OCP_4_N.5 43.34,-37.98 ; P_CPU_OCP_4_N.5 42.21,-37.98 ; P_CPU_OCP_4_N.5 42.21,-39.1 ; P_OCP_CPU_0_N.4 77.63,-27.5 ; P_OCP_CPU_0_N.4 77.63,-28.62 ; P_OCP_CPU_0_N.4 76.5,-27.5 ; P_OCP_CPU_0_N.4 76.5,-28.62 ; P_OCP_CPU_0_P.3 61.9,-28.62 ; P_OCP_CPU_0_P.3 60.77,-28.62 ; P_OCP_CPU_0_P.3 60.77,-27.5 ; P_OCP_CPU_0_P.3 61.9,-27.5 ; 30.78,-48.13 P_CPU_OCP_2_P.2 ; P_CPU_OCP_2_P.2 31.91,-47.01 ; P_CPU_OCP_2_P.2 31.91,-48.13 ; P_CPU_OCP_2_P.2 30.78,-47.01 ; 96.01,-11.86 P_BD1_CLK1_P.5 ; P_BD1_CLK1_P.5 97.14,-10.73 ; P_BD1_CLK1_P.5 97.14,-11.86 ; P_BD1_CLK1_P.5 96.01,-10.73 ; P_OCP_CPU_4_N.5 54.77,-39.1 ; P_OCP_CPU_4_N.5 53.64,-37.98 ; P_OCP_CPU_4_N.5 54.77,-37.98 ; P_OCP_CPU_4_N.5 53.64,-39.1 ; 86.98,-11.86 P_BD1_CLK1_N.2 ; P_BD1_CLK1_N.2 88.11,-11.86 ; P_BD1_CLK1_N.2 88.11,-10.73 ; P_BD1_CLK1_N.2 86.98,-10.73 ; P_CPU_OCP_2_N.4 31.91,-35.75 ; P_CPU_OCP_2_N.4 30.78,-35.75 ; P_CPU_OCP_2_N.4 30.78,-34.63 ; P_CPU_OCP_2_N.4 31.91,-34.63 ; 37.91,-37.98 P_CPU_OCP_4_N.2 ; P_CPU_OCP_4_N.2 37.91,-39.1 ; P_CPU_OCP_4_N.2 39.04,-37.98 ; P_CPU_OCP_4_N.2 39.04,-39.1 ; P_BD1_CLK0_P.3 54.77,-6.43 ; P_BD1_CLK0_P.3 54.77,-7.56 ; P_BD1_CLK0_P.3 53.64,-7.56 ; P_BD1_CLK0_P.3 53.64,-6.43 ; 99.36,-6.43 P_BD1_CLK1_P.3 ; P_BD1_CLK1_P.3 100.49,-6.43 ; P_BD1_CLK1_P.3 99.36,-7.56 ; P_BD1_CLK1_P.3 100.49,-7.56 ; P_BD1_CLK2_P.3 31.91,-6.43 ; P_BD1_CLK2_P.3 30.78,-6.43 ; P_BD1_CLK2_P.3 30.78,-7.56 ; P_BD1_CLK2_P.3 31.91,-7.56 ; 72.2,-58.61 P_OCP_CPU_5_N.3 ; P_OCP_CPU_5_N.3 72.2,-57.49 ; P_OCP_CPU_5_N.3 73.33,-57.49 ; P_OCP_CPU_5_N.3 73.33,-58.61 ; 73.15,-24.32 P_OCP_CPU_0_N.2 ; P_OCP_CPU_0_N.2 74.28,-23.2 ; P_OCP_CPU_0_N.2 73.15,-23.2 ; P_OCP_CPU_0_N.2 74.28,-24.32 ; P_CPU_OCP_4_N.3 39.04,-35.75 ; P_CPU_OCP_4_N.3 37.91,-35.75 ; P_CPU_OCP_4_N.3 39.04,-34.63 ; P_CPU_OCP_4_N.3 37.91,-34.63 ; P_CPU_OCP_3_P.5 16.18,-47.01 ; P_CPU_OCP_3_P.5 15.05,-47.01 ; P_CPU_OCP_3_P.5 15.05,-48.13 ; P_CPU_OCP_3_P.5 16.18,-48.13 ; P_CPU_OCP_0_N.4 16.18,-23.2 ; P_CPU_OCP_0_N.4 16.18,-24.32 ; P_CPU_OCP_0_N.4 15.05,-23.2 ; P_CPU_OCP_0_N.4 15.05,-24.32 ; 19.35,-73.22 P_CPU_OCP_7_P.3 ; P_CPU_OCP_7_P.3 19.35,-74.34 ; P_CPU_OCP_7_P.3 20.48,-74.34 ; P_CPU_OCP_7_P.3 20.48,-73.22 ; 18.4,-6.43 P_BD1_CLK2_N.5 ; P_BD1_CLK2_N.5 19.53,-7.56 ; P_BD1_CLK2_N.5 19.53,-6.43 ; P_BD1_CLK2_N.5 18.4,-7.56 ; P_BD1_CLK2_P.4 31.91,-10.73 ; P_BD1_CLK2_P.4 31.91,-11.86 ; P_BD1_CLK2_P.4 30.78,-10.73 ; P_BD1_CLK2_P.4 30.78,-11.86 ; P_CPU_OCP_6_N.3 27.61,-57.49 ; P_CPU_OCP_6_N.3 26.48,-57.49 ; P_CPU_OCP_6_N.3 26.48,-58.61 ; P_CPU_OCP_6_N.3 27.61,-58.61 ; 83.63,-7.56 P_BD1_CLK1_N.4 ; P_BD1_CLK1_N.4 83.63,-6.43 ; P_BD1_CLK1_N.4 84.76,-7.56 ; P_BD1_CLK1_N.4 84.76,-6.43 ; 83.63,-23.29 P_OCP_CPU_1_N.3 ; P_OCP_CPU_1_N.3 83.63,-22.16 ; P_OCP_CPU_1_N.3 84.76,-23.29 ; P_OCP_CPU_1_N.3 84.76,-22.16 ; P_OCP_CPU_2_N.4 77.63,-35.75 ; P_OCP_CPU_2_N.4 77.63,-34.63 ; P_OCP_CPU_2_N.4 76.5,-34.63 ; P_OCP_CPU_2_N.4 76.5,-35.75
  GD2 w0.254: 19.35,-60.84 P_CPU_OCP_7_N.5 ; P_CPU_OCP_7_N.5 19.35,-61.96 ; P_CPU_OCP_7_N.5 20.48,-60.84 ; P_CPU_OCP_7_N.5 20.48,-61.96 ; 76.5,-39.1 P_OCP_CPU_2_N.5 ; P_OCP_CPU_2_N.5 76.5,-37.98 ; P_OCP_CPU_2_N.5 77.63,-37.98 ; P_OCP_CPU_2_N.5 77.63,-39.1 ; P_CPU_OCP_2_P.2 31.91,-48.13 ; P_CPU_OCP_2_P.2 30.78,-47.01 ; P_CPU_OCP_2_P.2 30.78,-48.13 ; P_CPU_OCP_2_P.2 31.91,-47.01 ; P_CPU_OCP_2_P.4 27.61,-50.36 ; P_CPU_OCP_2_P.4 27.61,-51.48 ; P_CPU_OCP_2_P.4 26.48,-51.48 ; P_CPU_OCP_2_P.4 26.48,-50.36 ; P_CPU_OCP_4_P.5 39.04,-47.01 ; P_CPU_OCP_4_P.5 37.91,-47.01 ; P_CPU_OCP_4_P.5 39.04,-48.13 ; P_CPU_OCP_4_P.5 37.91,-48.13 ; 83.63,-73.22 P_BD1_TRIG_IN_N.4 ; P_BD1_TRIG_IN_N.4 84.76,-73.22 ; P_BD1_TRIG_IN_N.4 83.63,-74.34 ; P_BD1_TRIG_IN_N.4 84.76,-74.34 ; P_OCP_CPU_3_P.5 61.9,-47.01 ; P_OCP_CPU_3_P.5 61.9,-48.13 ; P_OCP_CPU_3_P.5 60.77,-48.13 ; P_OCP_CPU_3_P.5 60.77,-47.01 ; P_OCP_CPU_6_N.4 66.2,-57.49 ; P_OCP_CPU_6_N.4 66.2,-58.61 ; P_OCP_CPU_6_N.4 65.07,-57.49 ; P_OCP_CPU_6_N.4 65.07,-58.61 ; 96.33,-73.22 P_BD1_CMTS_P.4 ; P_BD1_CMTS_P.4 97.46,-74.34 ; P_BD1_CMTS_P.4 97.46,-73.22 ; P_BD1_CMTS_P.4 96.33,-74.34 ; P_CPU_OCP_4_N.5 43.34,-39.1 ; P_CPU_OCP_4_N.5 43.34,-37.98 ; P_CPU_OCP_4_N.5 42.21,-37.98 ; P_CPU_OCP_4_N.5 42.21,-39.1 ; 37.91,-7.56 P_BD1_CLK0_N.4 ; P_BD1_CLK0_N.4 39.04,-6.43 ; P_BD1_CLK0_N.4 39.04,-7.56 ; P_BD1_CLK0_N.4 37.91,-6.43 ; P_OCP_CPU_7_N.2 50.47,-61.96 ; P_OCP_CPU_7_N.2 50.47,-60.84 ; P_OCP_CPU_7_N.2 49.34,-61.96 ; P_OCP_CPU_7_N.2 49.34,-60.84 ; P_CPU_OCP_6_N.2 27.61,-60.84 ; P_CPU_OCP_6_N.2 27.61,-61.96 ; P_CPU_OCP_6_N.2 26.48,-61.96 ; P_CPU_OCP_6_N.2 26.48,-60.84 ; 53.64,-28.62 P_CPU_OCP_1_P.4 ; P_CPU_OCP_1_P.4 54.77,-28.62 ; P_CPU_OCP_1_P.4 53.64,-27.5 ; P_CPU_OCP_1_P.4 54.77,-27.5 ; 53.64,-70.99 P_OCP_CPU_7_P.2 ; P_OCP_CPU_7_P.2 54.77,-69.87 ; P_OCP_CPU_7_P.2 54.77,-70.99 ; P_OCP_CPU_7_P.2 53.64,-69.87 ; 96.33,-69.87 P_BD1_CMTS_P.5 ; P_BD1_CMTS_P.5 97.46,-70.99 ; P_BD1_CMTS_P.5 97.46,-69.87 ; P_BD1_CMTS_P.5 96.33,-70.99 ; P_BD1_CLK2_P.2 28.56,-6.43 ; P_BD1_CLK2_P.2 27.43,-7.56 ; P_BD1_CLK2_P.2 28.56,-7.56 ; P_BD1_CLK2_P.2 27.43,-6.43 ; P_BD1_CMTS_N.4 101.76,-58.61 ; P_BD1_CMTS_N.4 100.63,-58.61 ; P_BD1_CMTS_N.4 100.63,-57.49 ; P_BD1_CMTS_N.4 101.76,-57.49 ; 42.21,-51.48 P_CPU_OCP_4_P.3 ; P_CPU_OCP_4_P.3 43.34,-51.48 ; P_CPU_OCP_4_P.3 43.34,-50.36 ; P_CPU_OCP_4_P.3 42.21,-50.36 ; 15.05,-69.87 P_CPU_OCP_7_P.5 ; P_CPU_OCP_7_P.5 15.05,-70.99 ; P_CPU_OCP_7_P.5 16.18,-70.99 ; P_CPU_OCP_7_P.5 16.18,-69.87 ; P_CPU_OCP_2_P.5 27.61,-48.13 ; P_CPU_OCP_2_P.5 26.48,-48.13 ; P_CPU_OCP_2_P.5 27.61,-47.01 ; P_CPU_OCP_2_P.5 26.48,-47.01 ; 50.29,-28.62 P_CPU_OCP_1_P.5 ; P_CPU_OCP_1_P.5 51.42,-28.62 ; P_CPU_OCP_1_P.5 51.42,-27.5 ; P_CPU_OCP_1_P.5 50.29,-27.5 ; 30.78,-70.99 P_CPU_OCP_6_P.2 ; P_CPU_OCP_6_P.2 31.91,-69.87 ; P_CPU_OCP_6_P.2 30.78,-69.87 ; P_CPU_OCP_6_P.2 31.91,-70.99 ; P_BD1_CLK3_N.4 61.9,-6.43 ; P_BD1_CLK3_N.4 60.77,-6.43 ; P_BD1_CLK3_N.4 61.9,-7.56 ; P_BD1_CLK3_N.4 60.77,-7.56 ; P_OCP_CPU_7_N.3 50.47,-57.49 ; P_OCP_CPU_7_N.3 49.34,-57.49 ; P_OCP_CPU_7_N.3 50.47,-58.61 ; P_OCP_CPU_7_N.3 49.34,-58.61 ; 92.47,-35.34 P3.2 ; P3.2 93.94,-35.34 ; P3.2 93.94,-36.8 ; P3.2 92.47,-36.8 ; P_CPU_OCP_0_N.3 16.18,-28.62 ; P_CPU_OCP_0_N.3 15.05,-27.5 ; P_CPU_OCP_0_N.3 15.05,-28.62 ; P_CPU_OCP_0_N.3 16.18,-27.5 ; 83.63,-11.86 P_BD1_CLK1_N.3 ; P_BD1_CLK1_N.3 84.76,-11.86 ; P_BD1_CLK1_N.3 83.63,-10.73 ; P_BD1_CLK1_N.3 84.76,-10.73 ; 41.26,-7.56 P_BD1_CLK0_N.5 ; P_BD1_CLK0_N.5 42.39,-7.56 ; P_BD1_CLK0_N.5 42.39,-6.43 ; P_BD1_CLK0_N.5 41.26,-6.43 ; 60.77,-73.22 P_OCP_CPU_6_P.4 ; P_OCP_CPU_6_P.4 61.9,-74.34 ; P_OCP_CPU_6_P.4 61.9,-73.22 ; P_OCP_CPU_6_P.4 60.77,-74.34 ; P_CPU_OCP_0_P.3 31.91,-24.32 ; P_CPU_OCP_0_P.3 30.78,-24.32 ; P_CPU_OCP_0_P.3 30.78,-23.2 ; P_CPU_OCP_0_P.3 31.91,-23.2 ; P_CPU_OCP_0_P.5 28.56,-28.62 ; P_CPU_OCP_0_P.5 27.43,-28.62 ; P_CPU_OCP_0_P.5 28.56,-27.5 ; P_CPU_OCP_0_P.5 27.43,-27.5 ; P_CPU_OCP_6_P.4 27.61,-73.22 ; P_CPU_OCP_6_P.4 26.48,-74.34 ; P_CPU_OCP_6_P.4 27.61,-74.34 ; P_CPU_OCP_6_P.4 26.48,-73.22 ; 76.5,-47.01 P_OCP_CPU_2_P.2 ; P_OCP_CPU_2_P.2 77.63,-47.01 ; P_OCP_CPU_2_P.2 77.63,-48.13 ; P_OCP_CPU_2_P.2 76.5,-48.13 ; 41.26,-24.32 P_CPU_OCP_1_N.5 ; P_CPU_OCP_1_N.5 42.39,-24.32 ; P_CPU_OCP_1_N.5 41.26,-23.2 ; P_CPU_OCP_1_N.5 42.39,-23.2 ; P_BD1_CMTS_P.2 101.76,-70.99 ; P_BD1_CMTS_P.2 100.63,-69.87 ; P_BD1_CMTS_P.2 101.76,-69.87 ; P_BD1_CMTS_P.2 100.63,-70.99 ; P_OCP_CPU_0_N.4 77.63,-27.5 ; P_OCP_CPU_0_N.4 76.5,-27.5 ; P_OCP_CPU_0_N.4 76.5,-28.62 ; P_OCP_CPU_0_N.4 77.63,-28.62 ; 99.36,-22.16 P_OCP_CPU_1_P.4 ; P_OCP_CPU_1_P.4 100.49,-22.16 ; P_OCP_CPU_1_P.4 99.36,-23.29 ; P_OCP_CPU_1_P.4 100.49,-23.29 ; P_BD1_CLK3_P.3 77.63,-7.56 ; P_BD1_CLK3_P.3 77.63,-6.43 ; P_BD1_CLK3_P.3 76.5,-7.56 ; P_BD1_CLK3_P.3 76.5,-6.43 ; 99.36,-7.56 P_BD1_CLK1_P.3 ; P_BD1_CLK1_P.3 100.49,-7.56 ; P_BD1_CLK1_P.3 99.36,-6.43 ; P_BD1_CLK1_P.3 100.49,-6.43 ; P_CPU_OCP_5_N.2 39.04,-61.96 ; P_CPU_OCP_5_N.2 37.91,-60.84 ; P_CPU_OCP_5_N.2 37.91,-61.96 ; P_CPU_OCP_5_N.2 39.04,-60.84 ; 83.63,-61.96 P_BD1_TRIG_IN_P.2 ; P_BD1_TRIG_IN_P.2 84.76,-61.96 ; P_BD1_TRIG_IN_P.2 84.76,-60.84 ; P_BD1_TRIG_IN_P.2 83.63,-60.84 ; P_CPU_OCP_4_N.4 43.34,-35.75 ; P_CPU_OCP_4_N.4 42.21,-34.63 ; P_CPU_OCP_4_N.4 42.21,-35.75 ; P_CPU_OCP_4_N.4 43.34,-34.63 ; 37.91,-27.5 P_CPU_OCP_1_N.3 ; P_CPU_OCP_1_N.3 39.04,-28.62 ; P_CPU_OCP_1_N.3 39.04,-27.5 ; P_CPU_OCP_1_N.3 37.91,-28.62 ; P_CPU_OCP_0_N.4 16.18,-23.2 ; P_CPU_OCP_0_N.4 16.18,-24.32 ; P_CPU_OCP_0_N.4 15.05,-23.2 ; P_CPU_OCP_0_N.4 15.05,-24.32 ; 96.01,-22.16 P_OCP_CPU_1_P.5 ; P_OCP_CPU_1_P.5 97.14,-23.29 ; P_OCP_CPU_1_P.5 97.14,-22.16 ; P_OCP_CPU_1_P.5 96.01,-23.29 ; 72.2,-51.48 P_OCP_CPU_2_P.4 ; P_OCP_CPU_2_P.4 73.33,-51.48 ; P_OCP_CPU_2_P.4 72.2,-50.36 ; P_OCP_CPU_2_P.4 73.33,-50.36 ; 30.78,-39.1 P_CPU_OCP_2_N.5 ; P_CPU_OCP_2_N.5 31.91,-37.98 ; P_CPU_OCP_2_N.5 30.78,-37.98 ; P_CPU_OCP_2_N.5 31.91,-39.1 ; 49.34,-69.87 P_OCP_CPU_7_P.5 ; P_OCP_CPU_7_P.5 50.47,-69.87 ; P_OCP_CPU_7_P.5 49.34,-70.99 ; P_OCP_CPU_7_P.5 50.47,-70.99 ; 65.07,-34.63 P_OCP_CPU_3_N.4 ; P_OCP_CPU_3_N.4 66.2,-35.75 ; P_OCP_CPU_3_N.4 65.07,-35.75 ; P_OCP_CPU_3_N.4 66.2,-34.63 ; P_BD1_CLK0_P.2 51.42,-7.56 ; P_BD1_CLK0_P.2 50.29,-7.56 ; P_BD1_CLK0_P.2 50.29,-6.43 ; P_BD1_CLK0_P.2 51.42,-6.43 ; 65.07,-50.36 P_OCP_CPU_3_P.3 ; P_OCP_CPU_3_P.3 66.2,-50.36 ; P_OCP_CPU_3_P.3 65.07,-51.48 ; P_OCP_CPU_3_P.3 66.2,-51.48 ; P_BD1_CLK3_P.4 77.63,-10.73 ; P_BD1_CLK3_P.4 77.63,-11.86 ; P_BD1_CLK3_P.4 76.5,-11.86 ; P_BD1_CLK3_P.4 76.5,-10.73 ; 50.29,-23.2 P_CPU_OCP_1_P.2 ; P_CPU_OCP_1_P.2 51.42,-24.32 ; P_CPU_OCP_1_P.2 51.42,-23.2 ; P_CPU_OCP_1_P.2 50.29,-24.32 ; 27.43,-24.32 P_CPU_OCP_0_P.2 ; P_CPU_OCP_0_P.2 27.43,-23.2 ; P_CPU_OCP_0_P.2 28.56,-24.32 ; P_CPU_OCP_0_P.2 28.56,-23.2 ; P_OCP_CPU_4_N.3 50.47,-35.75 ; P_OCP_CPU_4_N.3 50.47,-34.63 ; P_OCP_CPU_4_N.3 49.34,-34.63 ; P_OCP_CPU_4_N.3 49.34,-35.75 ; 92.6,-29.69 P13.2 ; P13.2 92.6,-28.23 ; P13.2 94.06,-29.69 ; P13.2 94.06,-28.23 ; 18.4,-6.43 P_BD1_CLK2_N.5 ; P_BD1_CLK2_N.5 19.53,-6.43 ; P_BD1_CLK2_N.5 19.53,-7.56 ; P_BD1_CLK2_N.5 18.4,-7.56 ; 15.05,-34.63 P_CPU_OCP_3_N.3 ; P_CPU_OCP_3_N.3 15.05,-35.75 ; P_CPU_OCP_3_N.3 16.18,-34.63 ; P_CPU_OCP_3_N.3 16.18,-35.75 ; 26.48,-39.1 P_CPU_OCP_2_N.2 ; P_CPU_OCP_2_N.2 27.61,-37.98 ; P_CPU_OCP_2_N.2 26.48,-37.98 ; P_CPU_OCP_2_N.2 27.61,-39.1 ; P_OCP_CPU_0_N.5 74.28,-27.5 ; P_OCP_CPU_0_N.5 74.28,-28.62 ; P_OCP_CPU_0_N.5 73.15,-28.62 ; P_OCP_CPU_0_N.5 73.15,-27.5 ; 49.34,-37.98 P_OCP_CPU_4_N.2 ; P_OCP_CPU_4_N.2 50.47,-39.1 ; P_OCP_CPU_4_N.2 50.47,-37.98 ; P_OCP_CPU_4_N.2 49.34,-39.1 ; 83.63,-7.56 P_BD1_CLK1_N.4 ; P_BD1_CLK1_N.4 84.76,-7.56 ; P_BD1_CLK1_N.4 84.76,-6.43 ; P_BD1_CLK1_N.4 83.63,-6.43 ; 53.64,-37.98 P_OCP_CPU_4_N.5 ; P_OCP_CPU_4_N.5 54.77,-39.1 ; P_OCP_CPU_4_N.5 54.77,-37.98 ; P_OCP_CPU_4_N.5 53.64,-39.1 ; P_CPU_OCP_7_N.2 16.18,-60.84 ; P_CPU_OCP_7_N.2 15.05,-61.96 ; P_CPU_OCP_7_N.2 16.18,-61.96 ; P_CPU_OCP_7_N.2 15.05,-60.84 ; 72.2,-34.63 P_OCP_CPU_2_N.3 ; P_OCP_CPU_2_N.3 72.2,-35.75 ; P_OCP_CPU_2_N.3 73.33,-35.75 ; P_OCP_CPU_2_N.3 73.33,-34.63 ; 86.98,-17.86 P_OCP_CPU_1_N.5 ; P_OCP_CPU_1_N.5 86.98,-18.99 ; P_OCP_CPU_1_N.5 88.11,-17.86 ; P_OCP_CPU_1_N.5 88.11,-18.99 ; 73.15,-24.32 P_OCP_CPU_0_N.2 ; P_OCP_CPU_0_N.2 74.28,-24.32 ; P_OCP_CPU_0_N.2 73.15,-23.2 ; P_OCP_CPU_0_N.2 74.28,-23.2 ; 30.78,-74.34 P_CPU_OCP_6_P.3 ; P_CPU_OCP_6_P.3 31.91,-74.34 ; P_CPU_OCP_6_P.3 30.78,-73.22 ; P_CPU_OCP_6_P.3 31.91,-73.22 ; 72.2,-61.96 P_OCP_CPU_5_N.2 ; P_OCP_CPU_5_N.2 72.2,-60.84 ; P_OCP_CPU_5_N.2 73.33,-60.84 ; P_OCP_CPU_5_N.2 73.33,-61.96 ; P_BD1_TRIG_IN_P.4 89.06,-58.61 ; P_BD1_TRIG_IN_P.4 89.06,-57.49 ; P_BD1_TRIG_IN_P.4 87.93,-57.49 ; P_BD1_TRIG_IN_P.4 87.93,-58.61 ; P_OCP_CPU_1_N.4 84.76,-18.99 ; P_OCP_CPU_1_N.4 83.63,-17.86 ; P_OCP_CPU_1_N.4 84.76,-17.86 ; P_OCP_CPU_1_N.4 83.63,-18.99 ; P_CPU_OCP_5_N.4 43.34,-58.61 ; P_CPU_OCP_5_N.4 42.21,-57.49 ; P_CPU_OCP_5_N.4 42.21,-58.61 ; P_CPU_OCP_5_N.4 43.34,-57.49 ; 86.98,-23.29 P_OCP_CPU_1_N.2 ; P_OCP_CPU_1_N.2 88.11,-22.16 ; P_OCP_CPU_1_N.2 86.98,-22.16 ; P_OCP_CPU_1_N.2 88.11,-23.29 ; P_CPU_OCP_7_N.3 16.18,-58.61 ; P_CPU_OCP_7_N.3 15.05,-58.61 ; P_CPU_OCP_7_N.3 15.05,-57.49 ; P_CPU_OCP_7_N.3 16.18,-57.49 ; P_OCP_CPU_0_P.3 61.9,-28.62 ; P_OCP_CPU_0_P.3 60.77,-28.62 ; P_OCP_CPU_0_P.3 60.77,-27.5 ; P_OCP_CPU_0_P.3 61.9,-27.5 ; P_BD1_CLK2_N.2 19.53,-10.73 ; P_BD1_CLK2_N.2 18.4,-11.86 ; P_BD1_CLK2_N.2 18.4,-10.73 ; P_BD1_CLK2_N.2 19.53,-11.86 ; P_OCP_CPU_1_N.3 84.76,-23.29 ; P_OCP_CPU_1_N.3 83.63,-22.16 ; P_OCP_CPU_1_N.3 84.76,-22.16 ; P_OCP_CPU_1_N.3 83.63,-23.29 ; 65.07,-74.34 P_OCP_CPU_6_P.3 ; P_OCP_CPU_6_P.3 66.2,-73.22 ; P_OCP_CPU_6_P.3 65.07,-73.22 ; P_OCP_CPU_6_P.3 66.2,-74.34 ; 72.2,-58.61 P_OCP_CPU_5_N.3 ; P_OCP_CPU_5_N.3 73.33,-57.49 ; P_OCP_CPU_5_N.3 73.33,-58.61 ; P_OCP_CPU_5_N.3 72.2,-57.49 ; 65.07,-39.1 P_OCP_CPU_3_N.5 ; P_OCP_CPU_3_N.5 66.2,-37.98 ; P_OCP_CPU_3_N.5 65.07,-37.98 ; P_OCP_CPU_3_N.5 66.2,-39.1 ; P_CPU_OCP_2_P.3 31.91,-51.48 ; P_CPU_OCP_2_P.3 30.78,-51.48 ; P_CPU_OCP_2_P.3 31.91,-50.36 ; P_CPU_OCP_2_P.3 30.78,-50.36 ; P_OCP_CPU_5_P.3 77.63,-73.22 ; P_OCP_CPU_5_P.3 76.5,-73.22 ; P_OCP_CPU_5_P.3 76.5,-74.34 ; P_OCP_CPU_5_P.3 77.63,-74.34 ; P_BD1_CLK3_N.2 65.25,-10.73 ; P_BD1_CLK3_N.2 64.12,-11.86 ; P_BD1_CLK3_N.2 65.25,-11.86 ; P_BD1_CLK3_N.2 64.12,-10.73 ; 15.05,-39.1 P_CPU_OCP_3_N.2 ; P_CPU_OCP_3_N.2 15.05,-37.98 ; P_CPU_OCP_3_N.2 16.18,-39.1 ; P_CPU_OCP_3_N.2 16.18,-37.98 ; 65.07,-69.87 P_OCP_CPU_6_P.2 ; P_OCP_CPU_6_P.2 66.2,-69.87 ; P_OCP_CPU_6_P.2 66.2,-70.99 ; P_OCP_CPU_6_P.2 65.07,-70.99 ; 37.91,-37.98 P_CPU_OCP_4_N.2 ; P_CPU_OCP_4_N.2 39.04,-37.98 ; P_CPU_OCP_4_N.2 37.91,-39.1 ; P_CPU_OCP_4_N.2 39.04,-39.1 ; 53.64,-6.43 P_BD1_CLK0_P.3 ; P_BD1_CLK0_P.3 53.64,-7.56 ; P_BD1_CLK0_P.3 54.77,-6.43 ; P_BD1_CLK0_P.3 54.77,-7.56 ; P_CPU_OCP_6_N.5 31.91,-60.84 ; P_CPU_OCP_6_N.5 30.78,-61.96 ; P_CPU_OCP_6_N.5 31.91,-61.96 ; P_CPU_OCP_6_N.5 30.78,-60.84 ; P_OCP_CPU_4_P.5 50.47,-47.01 ; P_OCP_CPU_4_P.5 49.34,-47.01 ; P_OCP_CPU_4_P.5 49.34,-48.13 ; P_OCP_CPU_4_P.5 50.47,-48.13 ; P1.2 85.05,-35.34 ; P1.2 83.58,-35.34 ; P1.2 85.05,-36.8 ; P1.2 83.58,-36.8 ; 19.35,-74.34 P_CPU_OCP_7_P.3 ; P_CPU_OCP_7_P.3 20.48,-74.34 ; P_CPU_OCP_7_P.3 19.35,-73.22 ; P_CPU_OCP_7_P.3 20.48,-73.22 ; P_CPU_OCP_1_N.4 39.04,-24.32 ; P_CPU_OCP_1_N.4 37.91,-23.2 ; P_CPU_OCP_1_N.4 39.04,-23.2 ; P_CPU_OCP_1_N.4 37.91,-24.32 ; P_CPU_OCP_5_P.3 43.34,-74.34 ; P_CPU_OCP_5_P.3 42.21,-74.34 ; P_CPU_OCP_5_P.3 42.21,-73.22 ; P_CPU_OCP_5_P.3 43.34,-73.22 ; P_OCP_CPU_6_N.3 61.9,-57.49 ; P_OCP_CPU_6_N.3 61.9,-58.61 ; P_OCP_CPU_6_N.3 60.77,-58.61 ; P_OCP_CPU_6_N.3 60.77,-57.49 ; 15.05,-48.13 P_CPU_OCP_3_P.5 ; P_CPU_OCP_3_P.5 16.18,-47.01 ; P_CPU_OCP_3_P.5 15.05,-47.01 ; P_CPU_OCP_3_P.5 16.18,-48.13 ; 60.77,-50.36 P_OCP_CPU_3_P.4 ; P_OCP_CPU_3_P.4 61.9,-51.48 ; P_OCP_CPU_3_P.4 60.77,-51.48 ; P_OCP_CPU_3_P.4 61.9,-50.36 ; 30.78,-6.43 P_BD1_CLK2_P.3 ; P_BD1_CLK2_P.3 31.91,-7.56 ; P_BD1_CLK2_P.3 30.78,-7.56 ; P_BD1_CLK2_P.3 31.91,-6.43 ; P_BD1_CLK2_P.4 31.91,-11.86 ; P_BD1_CLK2_P.4 30.78,-10.73 ; P_BD1_CLK2_P.4 31.91,-10.73 ; P_BD1_CLK2_P.4 30.78,-11.86 ; 41.26,-28.62 P_CPU_OCP_1_N.2 ; P_CPU_OCP_1_N.2 42.39,-27.5 ; P_CPU_OCP_1_N.2 42.39,-28.62 ; P_CPU_OCP_1_N.2 41.26,-27.5 ; P_BD1_TRIG_IN_P.5 89.06,-60.84 ; P_BD1_TRIG_IN_P.5 89.06,-61.96 ; P_BD1_TRIG_IN_P.5 87.93,-61.96 ; P_BD1_TRIG_IN_P.5 87.93,-60.84 ; 72.2,-48.13 P_OCP_CPU_2_P.5 ; P_OCP_CPU_2_P.5 73.33,-48.13 ; P_OCP_CPU_2_P.5 72.2,-47.01 ; P_OCP_CPU_2_P.5 73.33,-47.01 ; 96.33,-61.96 P_BD1_CMTS_N.2 ; P_BD1_CMTS_N.2 97.46,-61.96 ; P_BD1_CMTS_N.2 97.46,-60.84 ; P_BD1_CMTS_N.2 96.33,-60.84 ; P_CPU_OCP_0_N.5 19.53,-23.2 ; P_CPU_OCP_0_N.5 19.53,-24.32 ; P_CPU_OCP_0_N.5 18.4,-24.32 ; P_CPU_OCP_0_N.5 18.4,-23.2 ; P_CPU_OCP_3_N.4 20.48,-35.75 ; P_CPU_OCP_3_N.4 19.35,-34.63 ; P_CPU_OCP_3_N.4 20.48,-34.63 ; P_CPU_OCP_3_N.4 19.35,-35.75 ; 83.63,-58.61 P_BD1_TRIG_IN_P.3 ; P_BD1_TRIG_IN_P.3 84.76,-57.49 ; P_BD1_TRIG_IN_P.3 84.76,-58.61 ; P_BD1_TRIG_IN_P.3 83.63,-57.49 ; P_OCP_CPU_5_P.4 73.33,-74.34 ; P_OCP_CPU_5_P.4 73.33,-73.22 ; P_OCP_CPU_5_P.4 72.2,-74.34 ; P_OCP_CPU_5_P.4 72.2,-73.22 ; P_BD1_CMTS_P.3 101.76,-74.34 ; P_BD1_CMTS_P.3 100.63,-73.22 ; P_BD1_CMTS_P.3 101.76,-73.22 ; P_BD1_CMTS_P.3 100.63,-74.34 ; P_CPU_OCP_5_N.5 43.34,-60.84 ; P_CPU_OCP_5_N.5 42.21,-60.84 ; P_CPU_OCP_5_N.5 43.34,-61.96 ; P_CPU_OCP_5_N.5 42.21,-61.96 ; P_BD1_CLK2_N.3 16.18,-10.73 ; P_BD1_CLK2_N.3 16.18,-11.86 ; P_BD1_CLK2_N.3 15.05,-11.86 ; P_BD1_CLK2_N.3 15.05,-10.73 ; P_BD1_CLK1_P.2 97.14,-6.43 ; P_BD1_CLK1_P.2 96.01,-7.56 ; P_BD1_CLK1_P.2 97.14,-7.56 ; P_BD1_CLK1_P.2 96.01,-6.43 ; P_OCP_CPU_7_P.3 54.77,-73.22 ; P_OCP_CPU_7_P.3 53.64,-73.22 ; P_OCP_CPU_7_P.3 53.64,-74.34 ; P_OCP_CPU_7_P.3 54.77,-74.34 ; 64.12,-28.62 P_OCP_CPU_0_P.2 ; P_OCP_CPU_0_P.2 64.12,-27.5 ; P_OCP_CPU_0_P.2 65.25,-27.5 ; P_OCP_CPU_0_P.2 65.25,-28.62 ; 30.78,-28.62 P_CPU_OCP_0_P.4 ; P_CPU_OCP_0_P.4 30.78,-27.5 ; P_CPU_OCP_0_P.4 31.91,-28.62 ; P_CPU_OCP_0_P.4 31.91,-27.5 ; P_CPU_OCP_5_P.4 39.04,-73.22 ; P_CPU_OCP_5_P.4 37.91,-73.22 ; P_CPU_OCP_5_P.4 37.91,-74.34 ; P_CPU_OCP_5_P.4 39.04,-74.34 ; P_CPU_OCP_7_N.4 20.48,-57.49 ; P_CPU_OCP_7_N.4 20.48,-58.61 ; P_CPU_OCP_7_N.4 19.35,-58.61 ; P_CPU_OCP_7_N.4 19.35,-57.49 ; P_OCP_CPU_5_N.4 77.63,-57.49 ; P_OCP_CPU_5_N.4 76.5,-57.49 ; P_OCP_CPU_5_N.4 76.5,-58.61 ; P_OCP_CPU_5_N.4 77.63,-58.61 ; P_OCP_CPU_3_P.2 66.2,-48.13 ; P_OCP_CPU_3_P.2 66.2,-47.01 ; P_OCP_CPU_3_P.2 65.07,-48.13 ; P_OCP_CPU_3_P.2 65.07,-47.01 ; 76.5,-69.87 P_OCP_CPU_5_P.2 ; P_OCP_CPU_5_P.2 76.5,-70.99 ; P_OCP_CPU_5_P.2 77.63,-69.87 ; P_OCP_CPU_5_P.2 77.63,-70.99 ; P_CPU_OCP_0_N.2 19.53,-27.5 ; P_CPU_OCP_0_N.2 18.4,-28.62 ; P_CPU_OCP_0_N.2 19.53,-28.62 ; P_CPU_OCP_0_N.2 18.4,-27.5 ; 86.98,-10.73 P_BD1_CLK1_N.2 ; P_BD1_CLK1_N.2 88.11,-11.86 ; P_BD1_CLK1_N.2 86.98,-11.86 ; P_BD1_CLK1_N.2 88.11,-10.73 ; 60.77,-23.2 P_OCP_CPU_0_P.4 ; P_OCP_CPU_0_P.4 61.9,-24.32 ; P_OCP_CPU_0_P.4 60.77,-24.32 ; P_OCP_CPU_0_P.4 61.9,-23.2 ; 96.01,-10.73 P_BD1_CLK1_P.5 ; P_BD1_CLK1_P.5 97.14,-11.86 ; P_BD1_CLK1_P.5 97.14,-10.73 ; P_BD1_CLK1_P.5 96.01,-11.86 ; P_CPU_OCP_2_N.3 27.61,-35.75 ; P_CPU_OCP_2_N.3 27.61,-34.63 ; P_CPU_OCP_2_N.3 26.48,-34.63 ; P_CPU_OCP_2_N.3 26.48,-35.75 ; 26.48,-58.61 P_CPU_OCP_6_N.3 ; P_CPU_OCP_6_N.3 27.61,-57.49 ; P_CPU_OCP_6_N.3 27.61,-58.61 ; P_CPU_OCP_6_N.3 26.48,-57.49 ; P_BD1_CLK3_N.3 61.9,-10.73 ; P_BD1_CLK3_N.3 61.9,-11.86 ; P_BD1_CLK3_N.3 60.77,-10.73 ; P_BD1_CLK3_N.3 60.77,-11.86 ; P_OCP_CPU_4_P.3 54.77,-50.36 ; P_OCP_CPU_4_P.3 53.64,-50.36 ; P_OCP_CPU_4_P.3 54.77,-51.48 ; P_OCP_CPU_4_P.3 53.64,-51.48 ; P_BD1_TRIG_IN_N.5 84.76,-70.99 ; P_BD1_TRIG_IN_N.5 83.63,-69.87 ; P_BD1_TRIG_IN_N.5 83.63,-70.99 ; P_BD1_TRIG_IN_N.5 84.76,-69.87 ; P_OCP_CPU_2_N.2 73.33,-39.1 ; P_OCP_CPU_2_N.2 72.2,-39.1 ; P_OCP_CPU_2_N.2 73.33,-37.98 ; P_OCP_CPU_2_N.2 72.2,-37.98 ; P_BD1_CMTS_N.3 97.46,-57.49 ; P_BD1_CMTS_N.3 96.33,-57.49 ; P_BD1_CMTS_N.3 97.46,-58.61 ; P_BD1_CMTS_N.3 96.33,-58.61 ; P_CPU_OCP_3_P.3 20.48,-51.48 ; P_CPU_OCP_3_P.3 19.35,-51.48 ; P_CPU_OCP_3_P.3 20.48,-50.36 ; P_CPU_OCP_3_P.3 19.35,-50.36 ; P_CPU_OCP_3_P.4 16.18,-50.36 ; P_CPU_OCP_3_P.4 15.05,-50.36 ; P_CPU_OCP_3_P.4 16.18,-51.48 ; P_CPU_OCP_3_P.4 15.05,-51.48 ; 72.2,-70.99 P_OCP_CPU_5_P.5 ; P_OCP_CPU_5_P.5 73.33,-69.87 ; P_OCP_CPU_5_P.5 73.33,-70.99 ; P_OCP_CPU_5_P.5 72.2,-69.87 ; 76.5,-60.84 P_OCP_CPU_5_N.5 ; P_OCP_CPU_5_N.5 76.5,-61.96 ; P_OCP_CPU_5_N.5 77.63,-60.84 ; P_OCP_CPU_5_N.5 77.63,-61.96 ; P_CPU_OCP_7_P.4 16.18,-74.34 ; P_CPU_OCP_7_P.4 15.05,-74.34 ; P_CPU_OCP_7_P.4 15.05,-73.22 ; P_CPU_OCP_7_P.4 16.18,-73.22 ; P_OCP_CPU_7_N.4 54.77,-57.49 ; P_OCP_CPU_7_N.4 53.64,-58.61 ; P_OCP_CPU_7_N.4 54.77,-58.61 ; P_OCP_CPU_7_N.4 53.64,-57.49 ; P_CPU_OCP_4_P.4 39.04,-50.36 ; P_CPU_OCP_4_P.4 37.91,-50.36 ; P_CPU_OCP_4_P.4 39.04,-51.48 ; P_CPU_OCP_4_P.4 37.91,-51.48 ; P_CPU_OCP_6_N.4 31.91,-57.49 ; P_CPU_OCP_6_N.4 30.78,-57.49 ; P_CPU_OCP_6_N.4 30.78,-58.61 ; P_CPU_OCP_6_N.4 31.91,-58.61 ; 99.36,-17.86 P_OCP_CPU_1_P.3 ; P_OCP_CPU_1_P.3 99.36,-18.99 ; P_OCP_CPU_1_P.3 100.49,-17.86 ; P_OCP_CPU_1_P.3 100.49,-18.99 ; P_OCP_CPU_0_N.3 77.63,-23.2 ; P_OCP_CPU_0_N.3 77.63,-24.32 ; P_OCP_CPU_0_N.3 76.5,-24.32 ; P_OCP_CPU_0_N.3 76.5,-23.2 ; 53.64,-48.13 P_OCP_CPU_4_P.2 ; P_OCP_CPU_4_P.2 54.77,-47.01 ; P_OCP_CPU_4_P.2 53.64,-47.01 ; P_OCP_CPU_4_P.2 54.77,-48.13 ; P_OCP_CPU_4_N.4 54.77,-35.75 ; P_OCP_CPU_4_N.4 53.64,-35.75 ; P_OCP_CPU_4_N.4 54.77,-34.63 ; P_OCP_CPU_4_N.4 53.64,-34.63 ; 19.35,-69.87 P_CPU_OCP_7_P.2 ; P_CPU_OCP_7_P.2 19.35,-70.99 ; P_CPU_OCP_7_P.2 20.48,-70.99 ; P_CPU_OCP_7_P.2 20.48,-69.87 ; P_BD1_CLK0_N.2 42.39,-10.73 ; P_BD1_CLK0_N.2 41.26,-10.73 ; P_BD1_CLK0_N.2 42.39,-11.86 ; P_BD1_CLK0_N.2 41.26,-11.86 ; P_BD1_CLK0_P.5 51.42,-10.73 ; P_BD1_CLK0_P.5 50.29,-11.86 ; P_BD1_CLK0_P.5 51.42,-11.86 ; P_BD1_CLK0_P.5 50.29,-10.73 ; P_BD1_CLK2_P.5 28.56,-11.86 ; P_BD1_CLK2_P.5 27.43,-10.73 ; P_BD1_CLK2_P.5 27.43,-11.86 ; P_BD1_CLK2_P.5 28.56,-10.73 ; 37.91,-10.73 P_BD1_CLK0_N.3 ; P_BD1_CLK0_N.3 37.91,-11.86 ; P_BD1_CLK0_N.3 39.04,-11.86 ; P_BD1_CLK0_N.3 39.04,-10.73 ; P_OCP_CPU_3_N.3 61.9,-34.63 ; P_OCP_CPU_3_N.3 60.77,-35.75 ; P_OCP_CPU_3_N.3 60.77,-34.63 ; P_OCP_CPU_3_N.3 61.9,-35.75 ; 37.91,-58.61 P_CPU_OCP_5_N.3 ; P_CPU_OCP_5_N.3 39.04,-57.49 ; P_CPU_OCP_5_N.3 39.04,-58.61 ; P_CPU_OCP_5_N.3 37.91,-57.49 ; P_OCP_CPU_2_P.3 77.63,-50.36 ; P_OCP_CPU_2_P.3 76.5,-50.36 ; P_OCP_CPU_2_P.3 76.5,-51.48 ; P_OCP_CPU_2_P.3 77.63,-51.48 ; P_CPU_OCP_5_P.5 39.04,-70.99 ; P_CPU_OCP_5_P.5 37.91,-69.87 ; P_CPU_OCP_5_P.5 37.91,-70.99 ; P_CPU_OCP_5_P.5 39.04,-69.87 ; P_BD1_CLK3_P.5 74.28,-11.86 ; P_BD1_CLK3_P.5 74.28,-10.73 ; P_BD1_CLK3_P.5 73.15,-10.73 ; P_BD1_CLK3_P.5 73.15,-11.86 ; 49.34,-51.48 P_OCP_CPU_4_P.4 ; P_OCP_CPU_4_P.4 50.47,-50.36 ; P_OCP_CPU_4_P.4 50.47,-51.48 ; P_OCP_CPU_4_P.4 49.34,-50.36 ; 65.07,-61.96 P_OCP_CPU_6_N.5 ; P_OCP_CPU_6_N.5 66.2,-60.84 ; P_OCP_CPU_6_N.5 66.2,-61.96 ; P_OCP_CPU_6_N.5 65.07,-60.84 ; P_BD1_CLK3_P.2 74.28,-6.43 ; P_BD1_CLK3_P.2 73.15,-6.43 ; P_BD1_CLK3_P.2 73.15,-7.56 ; P_BD1_CLK3_P.2 74.28,-7.56 ; P_BD1_CLK2_N.4 16.18,-6.43 ; P_BD1_CLK2_N.4 15.05,-6.43 ; P_BD1_CLK2_N.4 15.05,-7.56 ; P_BD1_CLK2_N.4 16.18,-7.56 ; P_CPU_OCP_3_N.5 20.48,-39.1 ; P_CPU_OCP_3_N.5 19.35,-37.98 ; P_CPU_OCP_3_N.5 19.35,-39.1 ; P_CPU_OCP_3_N.5 20.48,-37.98 ; P_BD1_TRIG_IN_N.2 89.06,-69.87 ; P_BD1_TRIG_IN_N.2 87.93,-69.87 ; P_BD1_TRIG_IN_N.2 87.93,-70.99 ; P_BD1_TRIG_IN_N.2 89.06,-70.99 ; 86.98,-7.56 P_BD1_CLK1_N.5 ; P_BD1_CLK1_N.5 88.11,-6.43 ; P_BD1_CLK1_N.5 88.11,-7.56 ; P_BD1_CLK1_N.5 86.98,-6.43 ; 53.64,-11.86 P_BD1_CLK0_P.4 ; P_BD1_CLK0_P.4 54.77,-10.73 ; P_BD1_CLK0_P.4 53.64,-10.73 ; P_BD1_CLK0_P.4 54.77,-11.86 ; P_OCP_CPU_6_P.5 61.9,-70.99 ; P_OCP_CPU_6_P.5 61.9,-69.87 ; P_OCP_CPU_6_P.5 60.77,-69.87 ; P_OCP_CPU_6_P.5 60.77,-70.99 ; 87.93,-73.22 P_BD1_TRIG_IN_N.3 ; P_BD1_TRIG_IN_N.3 87.93,-74.34 ; P_BD1_TRIG_IN_N.3 89.06,-74.34 ; P_BD1_TRIG_IN_N.3 89.06,-73.22 ; P_CPU_OCP_1_P.3 54.77,-24.32 ; P_CPU_OCP_1_P.3 54.77,-23.2 ; P_CPU_OCP_1_P.3 53.64,-24.32 ; P_CPU_OCP_1_P.3 53.64,-23.2 ; 64.12,-6.43 P_BD1_CLK3_N.5 ; P_BD1_CLK3_N.5 65.25,-6.43 ; P_BD1_CLK3_N.5 65.25,-7.56 ; P_BD1_CLK3_N.5 64.12,-7.56 ; 19.35,-48.13 P_CPU_OCP_3_P.2 ; P_CPU_OCP_3_P.2 20.48,-48.13 ; P_CPU_OCP_3_P.2 19.35,-47.01 ; P_CPU_OCP_3_P.2 20.48,-47.01 ; P_OCP_CPU_7_N.5 54.77,-61.96 ; P_OCP_CPU_7_N.5 53.64,-61.96 ; P_OCP_CPU_7_N.5 53.64,-60.84 ; P_OCP_CPU_7_N.5 54.77,-60.84 ; P_OCP_CPU_7_P.4 50.47,-73.22 ; P_OCP_CPU_7_P.4 50.47,-74.34 ; P_OCP_CPU_7_P.4 49.34,-74.34 ; P_OCP_CPU_7_P.4 49.34,-73.22 ; 88.02,-36.8 P2.2 ; P2.2 88.02,-35.34 ; P2.2 89.49,-35.34 ; P2.2 89.49,-36.8 ; P_CPU_OCP_2_N.4 31.91,-34.63 ; P_CPU_OCP_2_N.4 30.78,-34.63 ; P_CPU_OCP_2_N.4 31.91,-35.75 ; P_CPU_OCP_2_N.4 30.78,-35.75 ; P_OCP_CPU_6_N.2 61.9,-60.84 ; P_OCP_CPU_6_N.2 60.77,-60.84 ; P_OCP_CPU_6_N.2 61.9,-61.96 ; P_OCP_CPU_6_N.2 60.77,-61.96 ; 26.48,-69.87 P_CPU_OCP_6_P.5 ; P_CPU_OCP_6_P.5 27.61,-70.99 ; P_CPU_OCP_6_P.5 27.61,-69.87 ; P_CPU_OCP_6_P.5 26.48,-70.99 ; 99.36,-11.86 P_BD1_CLK1_P.4 ; P_BD1_CLK1_P.4 99.36,-10.73 ; P_BD1_CLK1_P.4 100.49,-11.86 ; P_BD1_CLK1_P.4 100.49,-10.73 ; P_OCP_CPU_0_P.5 65.25,-23.2 ; P_OCP_CPU_0_P.5 65.25,-24.32 ; P_OCP_CPU_0_P.5 64.12,-23.2 ; P_OCP_CPU_0_P.5 64.12,-24.32 ; P_CPU_OCP_4_N.3 39.04,-34.63 ; P_CPU_OCP_4_N.3 37.91,-35.75 ; P_CPU_OCP_4_N.3 37.91,-34.63 ; P_CPU_OCP_4_N.3 39.04,-35.75 ; 76.5,-35.75 P_OCP_CPU_2_N.4 ; P_OCP_CPU_2_N.4 77.63,-34.63 ; P_OCP_CPU_2_N.4 77.63,-35.75 ; P_OCP_CPU_2_N.4 76.5,-34.63 ; 42.21,-70.99 P_CPU_OCP_5_P.2 ; P_CPU_OCP_5_P.2 43.34,-70.99 ; P_CPU_OCP_5_P.2 43.34,-69.87 ; P_CPU_OCP_5_P.2 42.21,-69.87 ; 96.01,-18.99 P_OCP_CPU_1_P.2 ; P_OCP_CPU_1_P.2 96.01,-17.86 ; P_OCP_CPU_1_P.2 97.14,-17.86 ; P_OCP_CPU_1_P.2 97.14,-18.99 ; P_OCP_CPU_3_N.2 61.9,-37.98 ; P_OCP_CPU_3_N.2 60.77,-39.1 ; P_OCP_CPU_3_N.2 61.9,-39.1 ; P_OCP_CPU_3_N.2 60.77,-37.98 ; 100.63,-61.96 P_BD1_CMTS_N.5 ; P_BD1_CMTS_N.5 101.76,-60.84 ; P_BD1_CMTS_N.5 100.63,-60.84 ; P_BD1_CMTS_N.5 101.76,-61.96 ; 42.21,-48.13 P_CPU_OCP_4_P.2 ; P_CPU_OCP_4_P.2 42.21,-47.01 ; P_CPU_OCP_4_P.2 43.34,-48.13 ; P_CPU_OCP_4_P.2 43.34,-47.01
  GD3 w0.254: 15.05,-73.22 P_CPU_OCP_7_P.4 ; P_CPU_OCP_7_P.4 15.05,-74.34 ; P_CPU_OCP_7_P.4 16.18,-73.22 ; P_CPU_OCP_7_P.4 16.18,-74.34 ; P_CPU_OCP_6_N.2 27.61,-61.96 ; P_CPU_OCP_6_N.2 26.48,-61.96 ; P_CPU_OCP_6_N.2 26.48,-60.84 ; P_CPU_OCP_6_N.2 27.61,-60.84 ; 37.91,-23.2 P_CPU_OCP_1_N.4 ; P_CPU_OCP_1_N.4 39.04,-24.32 ; P_CPU_OCP_1_N.4 39.04,-23.2 ; P_CPU_OCP_1_N.4 37.91,-24.32 ; P_BD1_CLK1_N.2 88.11,-11.86 ; P_BD1_CLK1_N.2 86.98,-11.86 ; P_BD1_CLK1_N.2 86.98,-10.73 ; P_BD1_CLK1_N.2 88.11,-10.73 ; 60.77,-47.01 P_OCP_CPU_3_P.5 ; P_OCP_CPU_3_P.5 61.9,-47.01 ; P_OCP_CPU_3_P.5 61.9,-48.13 ; P_OCP_CPU_3_P.5 60.77,-48.13 ; 99.36,-7.56 P_BD1_CLK1_P.3 ; P_BD1_CLK1_P.3 99.36,-6.43 ; P_BD1_CLK1_P.3 100.49,-6.43 ; P_BD1_CLK1_P.3 100.49,-7.56 ; P_BD1_CLK0_P.3 54.77,-7.56 ; P_BD1_CLK0_P.3 54.77,-6.43 ; P_BD1_CLK0_P.3 53.64,-6.43 ; P_BD1_CLK0_P.3 53.64,-7.56 ; 96.33,-58.61 P_BD1_CMTS_N.3 ; P_BD1_CMTS_N.3 97.46,-58.61 ; P_BD1_CMTS_N.3 96.33,-57.49 ; P_BD1_CMTS_N.3 97.46,-57.49 ; P_CPU_OCP_1_P.4 54.77,-27.5 ; P_CPU_OCP_1_P.4 53.64,-27.5 ; P_CPU_OCP_1_P.4 54.77,-28.62 ; P_CPU_OCP_1_P.4 53.64,-28.62 ; P_OCP_CPU_3_P.2 66.2,-47.01 ; P_OCP_CPU_3_P.2 66.2,-48.13 ; P_OCP_CPU_3_P.2 65.07,-47.01 ; P_OCP_CPU_3_P.2 65.07,-48.13 ; P_CPU_OCP_4_P.4 39.04,-50.36 ; P_CPU_OCP_4_P.4 37.91,-51.48 ; P_CPU_OCP_4_P.4 39.04,-51.48 ; P_CPU_OCP_4_P.4 37.91,-50.36 ; 60.77,-6.43 P_BD1_CLK3_N.4 ; P_BD1_CLK3_N.4 60.77,-7.56 ; P_BD1_CLK3_N.4 61.9,-6.43 ; P_BD1_CLK3_N.4 61.9,-7.56 ; P_CPU_OCP_5_N.4 43.34,-57.49 ; P_CPU_OCP_5_N.4 43.34,-58.61 ; P_CPU_OCP_5_N.4 42.21,-57.49 ; P_CPU_OCP_5_N.4 42.21,-58.61 ; 26.48,-50.36 P_CPU_OCP_2_P.4 ; P_CPU_OCP_2_P.4 26.48,-51.48 ; P_CPU_OCP_2_P.4 27.61,-51.48 ; P_CPU_OCP_2_P.4 27.61,-50.36 ; P_CPU_OCP_3_N.2 16.18,-39.1 ; P_CPU_OCP_3_N.2 15.05,-37.98 ; P_CPU_OCP_3_N.2 15.05,-39.1 ; P_CPU_OCP_3_N.2 16.18,-37.98 ; 87.93,-73.22 P_BD1_TRIG_IN_N.3 ; P_BD1_TRIG_IN_N.3 89.06,-73.22 ; P_BD1_TRIG_IN_N.3 89.06,-74.34 ; P_BD1_TRIG_IN_N.3 87.93,-74.34 ; 65.07,-37.98 P_OCP_CPU_3_N.5 ; P_OCP_CPU_3_N.5 66.2,-37.98 ; P_OCP_CPU_3_N.5 65.07,-39.1 ; P_OCP_CPU_3_N.5 66.2,-39.1 ; 72.2,-70.99 P_OCP_CPU_5_P.5 ; P_OCP_CPU_5_P.5 72.2,-69.87 ; P_OCP_CPU_5_P.5 73.33,-70.99 ; P_OCP_CPU_5_P.5 73.33,-69.87 ; 96.33,-73.22 P_BD1_CMTS_P.4 ; P_BD1_CMTS_P.4 96.33,-74.34 ; P_BD1_CMTS_P.4 97.46,-74.34 ; P_BD1_CMTS_P.4 97.46,-73.22 ; P_CPU_OCP_6_N.4 31.91,-58.61 ; P_CPU_OCP_6_N.4 30.78,-58.61 ; P_CPU_OCP_6_N.4 30.78,-57.49 ; P_CPU_OCP_6_N.4 31.91,-57.49 ; P_BD1_CLK2_N.2 19.53,-11.86 ; P_BD1_CLK2_N.2 19.53,-10.73 ; P_BD1_CLK2_N.2 18.4,-10.73 ; P_BD1_CLK2_N.2 18.4,-11.86 ; P_OCP_CPU_4_N.3 50.47,-35.75 ; P_OCP_CPU_4_N.3 50.47,-34.63 ; P_OCP_CPU_4_N.3 49.34,-34.63 ; P_OCP_CPU_4_N.3 49.34,-35.75 ; 53.64,-69.87 P_OCP_CPU_7_P.2 ; P_OCP_CPU_7_P.2 54.77,-70.99 ; P_OCP_CPU_7_P.2 54.77,-69.87 ; P_OCP_CPU_7_P.2 53.64,-70.99 ; P_OCP_CPU_2_P.3 77.63,-50.36 ; P_OCP_CPU_2_P.3 77.63,-51.48 ; P_OCP_CPU_2_P.3 76.5,-50.36 ; P_OCP_CPU_2_P.3 76.5,-51.48 ; 26.48,-73.22 P_CPU_OCP_6_P.4 ; P_CPU_OCP_6_P.4 26.48,-74.34 ; P_CPU_OCP_6_P.4 27.61,-74.34 ; P_CPU_OCP_6_P.4 27.61,-73.22 ; 60.77,-24.32 P_OCP_CPU_0_P.4 ; P_OCP_CPU_0_P.4 61.9,-23.2 ; P_OCP_CPU_0_P.4 61.9,-24.32 ; P_OCP_CPU_0_P.4 60.77,-23.2 ; 19.35,-39.1 P_CPU_OCP_3_N.5 ; P_CPU_OCP_3_N.5 20.48,-37.98 ; P_CPU_OCP_3_N.5 19.35,-37.98 ; P_CPU_OCP_3_N.5 20.48,-39.1 ; 73.15,-27.5 P_OCP_CPU_0_N.5 ; P_OCP_CPU_0_N.5 73.15,-28.62 ; P_OCP_CPU_0_N.5 74.28,-28.62 ; P_OCP_CPU_0_N.5 74.28,-27.5 ; 72.2,-47.01 P_OCP_CPU_2_P.5 ; P_OCP_CPU_2_P.5 73.33,-47.01 ; P_OCP_CPU_2_P.5 73.33,-48.13 ; P_OCP_CPU_2_P.5 72.2,-48.13 ; P_BD1_CLK3_P.5 74.28,-11.86 ; P_BD1_CLK3_P.5 73.15,-11.86 ; P_BD1_CLK3_P.5 74.28,-10.73 ; P_BD1_CLK3_P.5 73.15,-10.73 ; P_CPU_OCP_1_P.2 51.42,-24.32 ; P_CPU_OCP_1_P.2 50.29,-24.32 ; P_CPU_OCP_1_P.2 51.42,-23.2 ; P_CPU_OCP_1_P.2 50.29,-23.2 ; 64.12,-10.73 P_BD1_CLK3_N.2 ; P_BD1_CLK3_N.2 65.25,-11.86 ; P_BD1_CLK3_N.2 65.25,-10.73 ; P_BD1_CLK3_N.2 64.12,-11.86 ; P_CPU_OCP_2_N.4 31.91,-34.63 ; P_CPU_OCP_2_N.4 30.78,-35.75 ; P_CPU_OCP_2_N.4 30.78,-34.63 ; P_CPU_OCP_2_N.4 31.91,-35.75 ; P_BD1_CLK2_N.4 16.18,-7.56 ; P_BD1_CLK2_N.4 15.05,-6.43 ; P_BD1_CLK2_N.4 15.05,-7.56 ; P_BD1_CLK2_N.4 16.18,-6.43 ; 83.63,-74.34 P_BD1_TRIG_IN_N.4 ; P_BD1_TRIG_IN_N.4 84.76,-73.22 ; P_BD1_TRIG_IN_N.4 84.76,-74.34 ; P_BD1_TRIG_IN_N.4 83.63,-73.22 ; P_CPU_OCP_5_N.2 39.04,-60.84 ; P_CPU_OCP_5_N.2 37.91,-61.96 ; P_CPU_OCP_5_N.2 37.91,-60.84 ; P_CPU_OCP_5_N.2 39.04,-61.96 ; 76.5,-57.49 P_OCP_CPU_5_N.4 ; P_OCP_CPU_5_N.4 76.5,-58.61 ; P_OCP_CPU_5_N.4 77.63,-57.49 ; P_OCP_CPU_5_N.4 77.63,-58.61 ; P_CPU_OCP_0_P.2 28.56,-23.2 ; P_CPU_OCP_0_P.2 28.56,-24.32 ; P_CPU_OCP_0_P.2 27.43,-23.2 ; P_CPU_OCP_0_P.2 27.43,-24.32 ; 86.98,-18.99 P_OCP_CPU_1_N.5 ; P_OCP_CPU_1_N.5 88.11,-17.86 ; P_OCP_CPU_1_N.5 88.11,-18.99 ; P_OCP_CPU_1_N.5 86.98,-17.86 ; P_OCP_CPU_1_N.3 84.76,-23.29 ; P_OCP_CPU_1_N.3 83.63,-22.16 ; P_OCP_CPU_1_N.3 84.76,-22.16 ; P_OCP_CPU_1_N.3 83.63,-23.29 ; P_OCP_CPU_1_P.5 97.14,-23.29 ; P_OCP_CPU_1_P.5 96.01,-22.16 ; P_OCP_CPU_1_P.5 97.14,-22.16 ; P_OCP_CPU_1_P.5 96.01,-23.29 ; 49.34,-70.99 P_OCP_CPU_7_P.5 ; P_OCP_CPU_7_P.5 50.47,-70.99 ; P_OCP_CPU_7_P.5 49.34,-69.87 ; P_OCP_CPU_7_P.5 50.47,-69.87 ; P_OCP_CPU_2_P.4 73.33,-50.36 ; P_OCP_CPU_2_P.4 73.33,-51.48 ; P_OCP_CPU_2_P.4 72.2,-50.36 ; P_OCP_CPU_2_P.4 72.2,-51.48 ; P_CPU_OCP_5_P.4 39.04,-74.34 ; P_CPU_OCP_5_P.4 39.04,-73.22 ; P_CPU_OCP_5_P.4 37.91,-74.34 ; P_CPU_OCP_5_P.4 37.91,-73.22 ; P_CPU_OCP_3_P.5 16.18,-47.01 ; P_CPU_OCP_3_P.5 15.05,-47.01 ; P_CPU_OCP_3_P.5 15.05,-48.13 ; P_CPU_OCP_3_P.5 16.18,-48.13 ; P_OCP_CPU_7_N.2 50.47,-61.96 ; P_OCP_CPU_7_N.2 50.47,-60.84 ; P_OCP_CPU_7_N.2 49.34,-61.96 ; P_OCP_CPU_7_N.2 49.34,-60.84 ; P_OCP_CPU_7_N.4 54.77,-57.49 ; P_OCP_CPU_7_N.4 54.77,-58.61 ; P_OCP_CPU_7_N.4 53.64,-58.61 ; P_OCP_CPU_7_N.4 53.64,-57.49 ; P_OCP_CPU_4_N.2 50.47,-37.98 ; P_OCP_CPU_4_N.2 49.34,-39.1 ; P_OCP_CPU_4_N.2 50.47,-39.1 ; P_OCP_CPU_4_N.2 49.34,-37.98 ; P_CPU_OCP_3_N.4 20.48,-35.75 ; P_CPU_OCP_3_N.4 20.48,-34.63 ; P_CPU_OCP_3_N.4 19.35,-34.63 ; P_CPU_OCP_3_N.4 19.35,-35.75 ; P_BD1_TRIG_IN_P.4 89.06,-58.61 ; P_BD1_TRIG_IN_P.4 89.06,-57.49 ; P_BD1_TRIG_IN_P.4 87.93,-57.49 ; P_BD1_TRIG_IN_P.4 87.93,-58.61 ; P_CPU_OCP_0_P.4 31.91,-28.62 ; P_CPU_OCP_0_P.4 30.78,-28.62 ; P_CPU_OCP_0_P.4 30.78,-27.5 ; P_CPU_OCP_0_P.4 31.91,-27.5 ; 26.48,-34.63 P_CPU_OCP_2_N.3 ; P_CPU_OCP_2_N.3 26.48,-35.75 ; P_CPU_OCP_2_N.3 27.61,-34.63 ; P_CPU_OCP_2_N.3 27.61,-35.75 ; P_CPU_OCP_1_P.5 51.42,-27.5 ; P_CPU_OCP_1_P.5 50.29,-28.62 ; P_CPU_OCP_1_P.5 50.29,-27.5 ; P_CPU_OCP_1_P.5 51.42,-28.62 ; 19.35,-57.49 P_CPU_OCP_7_N.4 ; P_CPU_OCP_7_N.4 20.48,-57.49 ; P_CPU_OCP_7_N.4 19.35,-58.61 ; P_CPU_OCP_7_N.4 20.48,-58.61 ; 72.2,-39.1 P_OCP_CPU_2_N.2 ; P_OCP_CPU_2_N.2 73.33,-39.1 ; P_OCP_CPU_2_N.2 73.33,-37.98 ; P_OCP_CPU_2_N.2 72.2,-37.98 ; P_BD1_CLK1_P.5 97.14,-10.73 ; P_BD1_CLK1_P.5 96.01,-10.73 ; P_BD1_CLK1_P.5 96.01,-11.86 ; P_BD1_CLK1_P.5 97.14,-11.86 ; 100.63,-73.22 P_BD1_CMTS_P.3 ; P_BD1_CMTS_P.3 100.63,-74.34 ; P_BD1_CMTS_P.3 101.76,-73.22 ; P_BD1_CMTS_P.3 101.76,-74.34 ; 65.07,-61.96 P_OCP_CPU_6_N.5 ; P_OCP_CPU_6_N.5 66.2,-61.96 ; P_OCP_CPU_6_N.5 66.2,-60.84 ; P_OCP_CPU_6_N.5 65.07,-60.84 ; 15.05,-57.49 P_CPU_OCP_7_N.3 ; P_CPU_OCP_7_N.3 15.05,-58.61 ; P_CPU_OCP_7_N.3 16.18,-58.61 ; P_CPU_OCP_7_N.3 16.18,-57.49 ; 99.36,-22.16 P_OCP_CPU_1_P.4 ; P_OCP_CPU_1_P.4 100.49,-23.29 ; P_OCP_CPU_1_P.4 100.49,-22.16 ; P_OCP_CPU_1_P.4 99.36,-23.29 ; P_CPU_OCP_1_N.2 42.39,-27.5 ; P_CPU_OCP_1_N.2 42.39,-28.62 ; P_CPU_OCP_1_N.2 41.26,-27.5 ; P_CPU_OCP_1_N.2 41.26,-28.62 ; 26.48,-39.1 P_CPU_OCP_2_N.2 ; P_CPU_OCP_2_N.2 26.48,-37.98 ; P_CPU_OCP_2_N.2 27.61,-37.98 ; P_CPU_OCP_2_N.2 27.61,-39.1 ; P_OCP_CPU_6_P.2 66.2,-69.87 ; P_OCP_CPU_6_P.2 65.07,-69.87 ; P_OCP_CPU_6_P.2 66.2,-70.99 ; P_OCP_CPU_6_P.2 65.07,-70.99 ; P_OCP_CPU_0_N.3 77.63,-24.32 ; P_OCP_CPU_0_N.3 76.5,-24.32 ; P_OCP_CPU_0_N.3 77.63,-23.2 ; P_OCP_CPU_0_N.3 76.5,-23.2 ; P_CPU_OCP_1_N.3 39.04,-27.5 ; P_CPU_OCP_1_N.3 37.91,-27.5 ; P_CPU_OCP_1_N.3 39.04,-28.62 ; P_CPU_OCP_1_N.3 37.91,-28.62 ; 37.91,-34.63 P_CPU_OCP_4_N.3 ; P_CPU_OCP_4_N.3 37.91,-35.75 ; P_CPU_OCP_4_N.3 39.04,-34.63 ; P_CPU_OCP_4_N.3 39.04,-35.75 ; P_CPU_OCP_0_P.5 28.56,-28.62 ; P_CPU_OCP_0_P.5 27.43,-27.5 ; P_CPU_OCP_0_P.5 28.56,-27.5 ; P_CPU_OCP_0_P.5 27.43,-28.62 ; P_OCP_CPU_6_P.3 66.2,-74.34 ; P_OCP_CPU_6_P.3 65.07,-74.34 ; P_OCP_CPU_6_P.3 66.2,-73.22 ; P_OCP_CPU_6_P.3 65.07,-73.22 ; P_CPU_OCP_4_N.4 43.34,-34.63 ; P_CPU_OCP_4_N.4 42.21,-35.75 ; P_CPU_OCP_4_N.4 42.21,-34.63 ; P_CPU_OCP_4_N.4 43.34,-35.75 ; 15.05,-51.48 P_CPU_OCP_3_P.4 ; P_CPU_OCP_3_P.4 16.18,-51.48 ; P_CPU_OCP_3_P.4 15.05,-50.36 ; P_CPU_OCP_3_P.4 16.18,-50.36 ; 76.5,-69.87 P_OCP_CPU_5_P.2 ; P_OCP_CPU_5_P.2 77.63,-70.99 ; P_OCP_CPU_5_P.2 77.63,-69.87 ; P_OCP_CPU_5_P.2 76.5,-70.99 ; 73.15,-24.32 P_OCP_CPU_0_N.2 ; P_OCP_CPU_0_N.2 74.28,-23.2 ; P_OCP_CPU_0_N.2 74.28,-24.32 ; P_OCP_CPU_0_N.2 73.15,-23.2 ; P_BD1_CLK2_P.2 28.56,-6.43 ; P_BD1_CLK2_P.2 28.56,-7.56 ; P_BD1_CLK2_P.2 27.43,-6.43 ; P_BD1_CLK2_P.2 27.43,-7.56 ; P2.2 89.49,-36.8 ; P2.2 88.02,-36.8 ; P2.2 89.49,-35.34 ; P2.2 88.02,-35.34 ; 92.6,-29.69 P13.2 ; P13.2 94.06,-29.69 ; P13.2 94.06,-28.23 ; P13.2 92.6,-28.23 ; 41.26,-10.73 P_BD1_CLK0_N.2 ; P_BD1_CLK0_N.2 42.39,-10.73 ; P_BD1_CLK0_N.2 42.39,-11.86 ; P_BD1_CLK0_N.2 41.26,-11.86 ; 30.78,-50.36 P_CPU_OCP_2_P.3 ; P_CPU_OCP_2_P.3 30.78,-51.48 ; P_CPU_OCP_2_P.3 31.91,-51.48 ; P_CPU_OCP_2_P.3 31.91,-50.36 ; P_CPU_OCP_7_P.3 20.48,-73.22 ; P_CPU_OCP_7_P.3 19.35,-73.22 ; P_CPU_OCP_7_P.3 19.35,-74.34 ; P_CPU_OCP_7_P.3 20.48,-74.34 ; 30.78,-69.87 P_CPU_OCP_6_P.2 ; P_CPU_OCP_6_P.2 31.91,-69.87 ; P_CPU_OCP_6_P.2 30.78,-70.99 ; P_CPU_OCP_6_P.2 31.91,-70.99 ; P_CPU_OCP_5_P.3 43.34,-73.22 ; P_CPU_OCP_5_P.3 42.21,-74.34 ; P_CPU_OCP_5_P.3 43.34,-74.34 ; P_CPU_OCP_5_P.3 42.21,-73.22 ; P_CPU_OCP_5_N.5 43.34,-61.96 ; P_CPU_OCP_5_N.5 42.21,-61.96 ; P_CPU_OCP_5_N.5 42.21,-60.84 ; P_CPU_OCP_5_N.5 43.34,-60.84 ; P_BD1_TRIG_IN_P.2 84.76,-60.84 ; P_BD1_TRIG_IN_P.2 84.76,-61.96 ; P_BD1_TRIG_IN_P.2 83.63,-60.84 ; P_BD1_TRIG_IN_P.2 83.63,-61.96 ; 99.36,-11.86 P_BD1_CLK1_P.4 ; P_BD1_CLK1_P.4 99.36,-10.73 ; P_BD1_CLK1_P.4 100.49,-10.73 ; P_BD1_CLK1_P.4 100.49,-11.86 ; 76.5,-39.1 P_OCP_CPU_2_N.5 ; P_OCP_CPU_2_N.5 77.63,-37.98 ; P_OCP_CPU_2_N.5 76.5,-37.98 ; P_OCP_CPU_2_N.5 77.63,-39.1 ; 19.35,-60.84 P_CPU_OCP_7_N.5 ; P_CPU_OCP_7_N.5 19.35,-61.96 ; P_CPU_OCP_7_N.5 20.48,-60.84 ; P_CPU_OCP_7_N.5 20.48,-61.96 ; P_CPU_OCP_2_N.5 31.91,-37.98 ; P_CPU_OCP_2_N.5 30.78,-39.1 ; P_CPU_OCP_2_N.5 31.91,-39.1 ; P_CPU_OCP_2_N.5 30.78,-37.98 ; 53.64,-60.84 P_OCP_CPU_7_N.5 ; P_OCP_CPU_7_N.5 54.77,-60.84 ; P_OCP_CPU_7_N.5 53.64,-61.96 ; P_OCP_CPU_7_N.5 54.77,-61.96 ; P_CPU_OCP_0_P.3 31.91,-23.2 ; P_CPU_OCP_0_P.3 30.78,-24.32 ; P_CPU_OCP_0_P.3 31.91,-24.32 ; P_CPU_OCP_0_P.3 30.78,-23.2 ; 53.64,-47.01 P_OCP_CPU_4_P.2 ; P_OCP_CPU_4_P.2 54.77,-47.01 ; P_OCP_CPU_4_P.2 54.77,-48.13 ; P_OCP_CPU_4_P.2 53.64,-48.13 ; 26.48,-57.49 P_CPU_OCP_6_N.3 ; P_CPU_OCP_6_N.3 27.61,-58.61 ; P_CPU_OCP_6_N.3 26.48,-58.61 ; P_CPU_OCP_6_N.3 27.61,-57.49 ; 76.5,-47.01 P_OCP_CPU_2_P.2 ; P_OCP_CPU_2_P.2 76.5,-48.13 ; P_OCP_CPU_2_P.2 77.63,-48.13 ; P_OCP_CPU_2_P.2 77.63,-47.01 ; P_CPU_OCP_0_N.5 19.53,-24.32 ; P_CPU_OCP_0_N.5 19.53,-23.2 ; P_CPU_OCP_0_N.5 18.4,-23.2 ; P_CPU_OCP_0_N.5 18.4,-24.32 ; 83.63,-58.61 P_BD1_TRIG_IN_P.3 ; P_BD1_TRIG_IN_P.3 84.76,-57.49 ; P_BD1_TRIG_IN_P.3 83.63,-57.49 ; P_BD1_TRIG_IN_P.3 84.76,-58.61 ; 50.29,-7.56 P_BD1_CLK0_P.2 ; P_BD1_CLK0_P.2 51.42,-6.43 ; P_BD1_CLK0_P.2 50.29,-6.43 ; P_BD1_CLK0_P.2 51.42,-7.56 ; 60.77,-74.34 P_OCP_CPU_6_P.4 ; P_OCP_CPU_6_P.4 61.9,-73.22 ; P_OCP_CPU_6_P.4 60.77,-73.22 ; P_OCP_CPU_6_P.4 61.9,-74.34 ; P_CPU_OCP_5_P.5 39.04,-69.87 ; P_CPU_OCP_5_P.5 37.91,-69.87 ; P_CPU_OCP_5_P.5 37.91,-70.99 ; P_CPU_OCP_5_P.5 39.04,-70.99 ; P_OCP_CPU_1_N.4 84.76,-18.99 ; P_OCP_CPU_1_N.4 83.63,-18.99 ; P_OCP_CPU_1_N.4 84.76,-17.86 ; P_OCP_CPU_1_N.4 83.63,-17.86 ; P_BD1_CLK0_P.5 51.42,-10.73 ; P_BD1_CLK0_P.5 50.29,-11.86 ; P_BD1_CLK0_P.5 51.42,-11.86 ; P_BD1_CLK0_P.5 50.29,-10.73 ; 60.77,-35.75 P_OCP_CPU_3_N.3 ; P_OCP_CPU_3_N.3 61.9,-35.75 ; P_OCP_CPU_3_N.3 61.9,-34.63 ; P_OCP_CPU_3_N.3 60.77,-34.63 ; P_BD1_CMTS_P.5 97.46,-70.99 ; P_BD1_CMTS_P.5 96.33,-69.87 ; P_BD1_CMTS_P.5 97.46,-69.87 ; P_BD1_CMTS_P.5 96.33,-70.99 ; 76.5,-7.56 P_BD1_CLK3_P.3 ; P_BD1_CLK3_P.3 76.5,-6.43 ; P_BD1_CLK3_P.3 77.63,-7.56 ; P_BD1_CLK3_P.3 77.63,-6.43 ; P_OCP_CPU_3_P.4 61.9,-50.36 ; P_OCP_CPU_3_P.4 60.77,-50.36 ; P_OCP_CPU_3_P.4 61.9,-51.48 ; P_OCP_CPU_3_P.4 60.77,-51.48 ; P_OCP_CPU_4_P.3 54.77,-51.48 ; P_OCP_CPU_4_P.3 53.64,-51.48 ; P_OCP_CPU_4_P.3 53.64,-50.36 ; P_OCP_CPU_4_P.3 54.77,-50.36 ; P_OCP_CPU_7_N.3 50.47,-58.61 ; P_OCP_CPU_7_N.3 49.34,-58.61 ; P_OCP_CPU_7_N.3 49.34,-57.49 ; P_OCP_CPU_7_N.3 50.47,-57.49 ; 49.34,-73.22 P_OCP_CPU_7_P.4 ; P_OCP_CPU_7_P.4 50.47,-74.34 ; P_OCP_CPU_7_P.4 50.47,-73.22 ; P_OCP_CPU_7_P.4 49.34,-74.34 ; 76.5,-28.62 P_OCP_CPU_0_N.4 ; P_OCP_CPU_0_N.4 77.63,-27.5 ; P_OCP_CPU_0_N.4 76.5,-27.5 ; P_OCP_CPU_0_N.4 77.63,-28.62 ; P_CPU_OCP_2_P.5 27.61,-48.13 ; P_CPU_OCP_2_P.5 27.61,-47.01 ; P_CPU_OCP_2_P.5 26.48,-47.01 ; P_CPU_OCP_2_P.5 26.48,-48.13 ; 96.01,-18.99 P_OCP_CPU_1_P.2 ; P_OCP_CPU_1_P.2 97.14,-17.86 ; P_OCP_CPU_1_P.2 96.01,-17.86 ; P_OCP_CPU_1_P.2 97.14,-18.99 ; 30.78,-48.13 P_CPU_OCP_2_P.2 ; P_CPU_OCP_2_P.2 30.78,-47.01 ; P_CPU_OCP_2_P.2 31.91,-48.13 ; P_CPU_OCP_2_P.2 31.91,-47.01 ; P_CPU_OCP_6_N.5 31.91,-60.84 ; P_CPU_OCP_6_N.5 30.78,-60.84 ; P_CPU_OCP_6_N.5 31.91,-61.96 ; P_CPU_OCP_6_N.5 30.78,-61.96 ; 60.77,-57.49 P_OCP_CPU_6_N.3 ; P_OCP_CPU_6_N.3 61.9,-57.49 ; P_OCP_CPU_6_N.3 61.9,-58.61 ; P_OCP_CPU_6_N.3 60.77,-58.61 ; P_CPU_OCP_0_N.2 19.53,-27.5 ; P_CPU_OCP_0_N.2 18.4,-28.62 ; P_CPU_OCP_0_N.2 19.53,-28.62 ; P_CPU_OCP_0_N.2 18.4,-27.5 ; 76.5,-73.22 P_OCP_CPU_5_P.3 ; P_OCP_CPU_5_P.3 77.63,-74.34 ; P_OCP_CPU_5_P.3 76.5,-74.34 ; P_OCP_CPU_5_P.3 77.63,-73.22 ; 49.34,-47.01 P_OCP_CPU_4_P.5 ; P_OCP_CPU_4_P.5 50.47,-48.13 ; P_OCP_CPU_4_P.5 49.34,-48.13 ; P_OCP_CPU_4_P.5 50.47,-47.01 ; P_OCP_CPU_6_N.4 66.2,-57.49 ; P_OCP_CPU_6_N.4 66.2,-58.61 ; P_OCP_CPU_6_N.4 65.07,-57.49 ; P_OCP_CPU_6_N.4 65.07,-58.61 ; 30.78,-74.34 P_CPU_OCP_6_P.3 ; P_CPU_OCP_6_P.3 30.78,-73.22 ; P_CPU_OCP_6_P.3 31.91,-74.34 ; P_CPU_OCP_6_P.3 31.91,-73.22 ; P_OCP_CPU_3_P.3 66.2,-51.48 ; P_OCP_CPU_3_P.3 65.07,-51.48 ; P_OCP_CPU_3_P.3 65.07,-50.36 ; P_OCP_CPU_3_P.3 66.2,-50.36 ; P_BD1_CLK1_N.4 84.76,-6.43 ; P_BD1_CLK1_N.4 83.63,-7.56 ; P_BD1_CLK1_N.4 83.63,-6.43 ; P_BD1_CLK1_N.4 84.76,-7.56 ; 37.91,-47.01 P_CPU_OCP_4_P.5 ; P_CPU_OCP_4_P.5 39.04,-47.01 ; P_CPU_OCP_4_P.5 39.04,-48.13 ; P_CPU_OCP_4_P.5 37.91,-48.13 ; P_CPU_OCP_4_P.3 43.34,-51.48 ; P_CPU_OCP_4_P.3 42.21,-50.36 ; P_CPU_OCP_4_P.3 43.34,-50.36 ; P_CPU_OCP_4_P.3 42.21,-51.48 ; P_CPU_OCP_4_N.5 43.34,-39.1 ; P_CPU_OCP_4_N.5 43.34,-37.98 ; P_CPU_OCP_4_N.5 42.21,-39.1 ; P_CPU_OCP_4_N.5 42.21,-37.98 ; P_OCP_CPU_2_N.4 77.63,-34.63 ; P_OCP_CPU_2_N.4 76.5,-35.75 ; P_OCP_CPU_2_N.4 76.5,-34.63 ; P_OCP_CPU_2_N.4 77.63,-35.75 ; 100.63,-69.87 P_BD1_CMTS_P.2 ; P_BD1_CMTS_P.2 100.63,-70.99 ; P_BD1_CMTS_P.2 101.76,-69.87 ; P_BD1_CMTS_P.2 101.76,-70.99 ; 99.36,-17.86 P_OCP_CPU_1_P.3 ; P_OCP_CPU_1_P.3 100.49,-18.99 ; P_OCP_CPU_1_P.3 99.36,-18.99 ; P_OCP_CPU_1_P.3 100.49,-17.86 ; P_BD1_CLK3_N.5 65.25,-6.43 ; P_BD1_CLK3_N.5 64.12,-6.43 ; P_BD1_CLK3_N.5 65.25,-7.56 ; P_BD1_CLK3_N.5 64.12,-7.56 ; 15.05,-61.96 P_CPU_OCP_7_N.2 ; P_CPU_OCP_7_N.2 15.05,-60.84 ; P_CPU_OCP_7_N.2 16.18,-61.96 ; P_CPU_OCP_7_N.2 16.18,-60.84 ; P_BD1_CMTS_N.2 97.46,-60.84 ; P_BD1_CMTS_N.2 97.46,-61.96 ; P_BD1_CMTS_N.2 96.33,-60.84 ; P_BD1_CMTS_N.2 96.33,-61.96 ; P_BD1_CLK2_N.5 19.53,-7.56 ; P_BD1_CLK2_N.5 19.53,-6.43 ; P_BD1_CLK2_N.5 18.4,-7.56 ; P_BD1_CLK2_N.5 18.4,-6.43 ; 53.64,-34.63 P_OCP_CPU_4_N.4 ; P_OCP_CPU_4_N.4 54.77,-35.75 ; P_OCP_CPU_4_N.4 54.77,-34.63 ; P_OCP_CPU_4_N.4 53.64,-35.75 ; P_CPU_OCP_6_P.5 27.61,-70.99 ; P_CPU_OCP_6_P.5 26.48,-70.99 ; P_CPU_OCP_6_P.5 27.61,-69.87 ; P_CPU_OCP_6_P.5 26.48,-69.87 ; P_BD1_CLK0_N.4 39.04,-7.56 ; P_BD1_CLK0_N.4 37.91,-7.56 ; P_BD1_CLK0_N.4 37.91,-6.43 ; P_BD1_CLK0_N.4 39.04,-6.43 ; 87.93,-61.96 P_BD1_TRIG_IN_P.5 ; P_BD1_TRIG_IN_P.5 89.06,-61.96 ; P_BD1_TRIG_IN_P.5 89.06,-60.84 ; P_BD1_TRIG_IN_P.5 87.93,-60.84 ; P_OCP_CPU_0_P.5 65.25,-23.2 ; P_OCP_CPU_0_P.5 64.12,-23.2 ; P_OCP_CPU_0_P.5 65.25,-24.32 ; P_OCP_CPU_0_P.5 64.12,-24.32 ; 96.01,-7.56 P_BD1_CLK1_P.2 ; P_BD1_CLK1_P.2 96.01,-6.43 ; P_BD1_CLK1_P.2 97.14,-7.56 ; P_BD1_CLK1_P.2 97.14,-6.43 ; 83.58,-36.8 P1.2 ; P1.2 85.05,-35.34 ; P1.2 83.58,-35.34 ; P1.2 85.05,-36.8 ; P_OCP_CPU_1_N.2 88.11,-22.16 ; P_OCP_CPU_1_N.2 86.98,-23.29 ; P_OCP_CPU_1_N.2 86.98,-22.16 ; P_OCP_CPU_1_N.2 88.11,-23.29 ; P_CPU_OCP_0_N.4 16.18,-24.32 ; P_CPU_OCP_0_N.4 16.18,-23.2 ; P_CPU_OCP_0_N.4 15.05,-24.32 ; P_CPU_OCP_0_N.4 15.05,-23.2 ; 76.5,-60.84 P_OCP_CPU_5_N.5 ; P_OCP_CPU_5_N.5 77.63,-60.84 ; P_OCP_CPU_5_N.5 77.63,-61.96 ; P_OCP_CPU_5_N.5 76.5,-61.96 ; P_BD1_CLK0_N.3 39.04,-11.86 ; P_BD1_CLK0_N.3 37.91,-11.86 ; P_BD1_CLK0_N.3 37.91,-10.73 ; P_BD1_CLK0_N.3 39.04,-10.73 ; P_OCP_CPU_2_N.3 73.33,-34.63 ; P_OCP_CPU_2_N.3 73.33,-35.75 ; P_OCP_CPU_2_N.3 72.2,-34.63 ; P_OCP_CPU_2_N.3 72.2,-35.75 ; 53.64,-37.98 P_OCP_CPU_4_N.5 ; P_OCP_CPU_4_N.5 54.77,-37.98 ; P_OCP_CPU_4_N.5 53.64,-39.1 ; P_OCP_CPU_4_N.5 54.77,-39.1 ; P_CPU_OCP_3_N.3 16.18,-35.75 ; P_CPU_OCP_3_N.3 15.05,-35.75 ; P_CPU_OCP_3_N.3 15.05,-34.63 ; P_CPU_OCP_3_N.3 16.18,-34.63 ; 37.91,-58.61 P_CPU_OCP_5_N.3 ; P_CPU_OCP_5_N.3 39.04,-57.49 ; P_CPU_OCP_5_N.3 37.91,-57.49 ; P_CPU_OCP_5_N.3 39.04,-58.61 ; P_OCP_CPU_3_N.2 61.9,-39.1 ; P_OCP_CPU_3_N.2 60.77,-37.98 ; P_OCP_CPU_3_N.2 61.9,-37.98 ; P_OCP_CPU_3_N.2 60.77,-39.1 ; 19.35,-48.13 P_CPU_OCP_3_P.2 ; P_CPU_OCP_3_P.2 20.48,-48.13 ; P_CPU_OCP_3_P.2 20.48,-47.01 ; P_CPU_OCP_3_P.2 19.35,-47.01 ; P_CPU_OCP_1_P.3 54.77,-24.32 ; P_CPU_OCP_1_P.3 53.64,-23.2 ; P_CPU_OCP_1_P.3 54.77,-23.2 ; P_CPU_OCP_1_P.3 53.64,-24.32 ; P_BD1_CLK0_P.4 54.77,-11.86 ; P_BD1_CLK0_P.4 53.64,-10.73 ; P_BD1_CLK0_P.4 53.64,-11.86 ; P_BD1_CLK0_P.4 54.77,-10.73 ; 60.77,-28.62 P_OCP_CPU_0_P.3 ; P_OCP_CPU_0_P.3 61.9,-27.5 ; P_OCP_CPU_0_P.3 61.9,-28.62 ; P_OCP_CPU_0_P.3 60.77,-27.5 ; 27.43,-10.73 P_BD1_CLK2_P.5 ; P_BD1_CLK2_P.5 28.56,-11.86 ; P_BD1_CLK2_P.5 27.43,-11.86 ; P_BD1_CLK2_P.5 28.56,-10.73 ; 64.12,-28.62 P_OCP_CPU_0_P.2 ; P_OCP_CPU_0_P.2 65.25,-27.5 ; P_OCP_CPU_0_P.2 64.12,-27.5 ; P_OCP_CPU_0_P.2 65.25,-28.62 ; P_BD1_CLK0_N.5 42.39,-7.56 ; P_BD1_CLK0_N.5 42.39,-6.43 ; P_BD1_CLK0_N.5 41.26,-6.43 ; P_BD1_CLK0_N.5 41.26,-7.56 ; P_OCP_CPU_5_N.2 73.33,-61.96 ; P_OCP_CPU_5_N.2 72.2,-61.96 ; P_OCP_CPU_5_N.2 72.2,-60.84 ; P_OCP_CPU_5_N.2 73.33,-60.84 ; 42.21,-48.13 P_CPU_OCP_4_P.2 ; P_CPU_OCP_4_P.2 43.34,-47.01 ; P_CPU_OCP_4_P.2 43.34,-48.13 ; P_CPU_OCP_4_P.2 42.21,-47.01 ; 41.26,-23.2 P_CPU_OCP_1_N.5 ; P_CPU_OCP_1_N.5 42.39,-23.2 ; P_CPU_OCP_1_N.5 41.26,-24.32 ; P_CPU_OCP_1_N.5 42.39,-24.32 ; P_BD1_CLK3_P.2 74.28,-6.43 ; P_BD1_CLK3_P.2 73.15,-7.56 ; P_BD1_CLK3_P.2 73.15,-6.43 ; P_BD1_CLK3_P.2 74.28,-7.56 ; 30.78,-11.86 P_BD1_CLK2_P.4 ; P_BD1_CLK2_P.4 31.91,-10.73 ; P_BD1_CLK2_P.4 31.91,-11.86 ; P_BD1_CLK2_P.4 30.78,-10.73 ; P_OCP_CPU_3_N.4 66.2,-35.75 ; P_OCP_CPU_3_N.4 66.2,-34.63 ; P_OCP_CPU_3_N.4 65.07,-35.75 ; P_OCP_CPU_3_N.4 65.07,-34.63 ; 19.35,-50.36 P_CPU_OCP_3_P.3 ; P_CPU_OCP_3_P.3 19.35,-51.48 ; P_CPU_OCP_3_P.3 20.48,-50.36 ; P_CPU_OCP_3_P.3 20.48,-51.48 ; 72.2,-58.61 P_OCP_CPU_5_N.3 ; P_OCP_CPU_5_N.3 73.33,-57.49 ; P_OCP_CPU_5_N.3 72.2,-57.49 ; P_OCP_CPU_5_N.3 73.33,-58.61 ; 83.63,-70.99 P_BD1_TRIG_IN_N.5 ; P_BD1_TRIG_IN_N.5 84.76,-69.87 ; P_BD1_TRIG_IN_N.5 83.63,-69.87 ; P_BD1_TRIG_IN_N.5 84.76,-70.99 ; 49.34,-50.36 P_OCP_CPU_4_P.4 ; P_OCP_CPU_4_P.4 50.47,-51.48 ; P_OCP_CPU_4_P.4 50.47,-50.36 ; P_OCP_CPU_4_P.4 49.34,-51.48 ; 100.63,-57.49 P_BD1_CMTS_N.4 ; P_BD1_CMTS_N.4 100.63,-58.61 ; P_BD1_CMTS_N.4 101.76,-57.49 ; P_BD1_CMTS_N.4 101.76,-58.61 ; P_BD1_CLK2_P.3 31.91,-6.43 ; P_BD1_CLK2_P.3 31.91,-7.56 ; P_BD1_CLK2_P.3 30.78,-6.43 ; P_BD1_CLK2_P.3 30.78,-7.56 ; 83.63,-11.86 P_BD1_CLK1_N.3 ; P_BD1_CLK1_N.3 84.76,-10.73 ; P_BD1_CLK1_N.3 83.63,-10.73 ; P_BD1_CLK1_N.3 84.76,-11.86 ; P_BD1_CLK3_P.4 77.63,-11.86 ; P_BD1_CLK3_P.4 76.5,-10.73 ; P_BD1_CLK3_P.4 76.5,-11.86 ; P_BD1_CLK3_P.4 77.63,-10.73 ; P_BD1_CMTS_N.5 101.76,-60.84 ; P_BD1_CMTS_N.5 100.63,-60.84 ; P_BD1_CMTS_N.5 101.76,-61.96 ; P_BD1_CMTS_N.5 100.63,-61.96 ; 86.98,-6.43 P_BD1_CLK1_N.5 ; P_BD1_CLK1_N.5 86.98,-7.56 ; P_BD1_CLK1_N.5 88.11,-6.43 ; P_BD1_CLK1_N.5 88.11,-7.56 ; P_CPU_OCP_0_N.3 16.18,-27.5 ; P_CPU_OCP_0_N.3 15.05,-27.5 ; P_CPU_OCP_0_N.3 16.18,-28.62 ; P_CPU_OCP_0_N.3 15.05,-28.62 ; P_BD1_CLK2_N.3 16.18,-10.73 ; P_BD1_CLK2_N.3 16.18,-11.86 ; P_BD1_CLK2_N.3 15.05,-11.86 ; P_BD1_CLK2_N.3 15.05,-10.73 ; P_CPU_OCP_4_N.2 39.04,-37.98 ; P_CPU_OCP_4_N.2 39.04,-39.1 ; P_CPU_OCP_4_N.2 37.91,-37.98 ; P_CPU_OCP_4_N.2 37.91,-39.1 ; P_CPU_OCP_5_P.2 43.34,-70.99 ; P_CPU_OCP_5_P.2 43.34,-69.87 ; P_CPU_OCP_5_P.2 42.21,-70.99 ; P_CPU_OCP_5_P.2 42.21,-69.87 ; 53.64,-74.34 P_OCP_CPU_7_P.3 ; P_OCP_CPU_7_P.3 54.77,-74.34 ; P_OCP_CPU_7_P.3 53.64,-73.22 ; P_OCP_CPU_7_P.3 54.77,-73.22 ; 92.47,-36.8 P3.2 ; P3.2 92.47,-35.34 ; P3.2 93.94,-36.8 ; P3.2 93.94,-35.34 ; P_CPU_OCP_7_P.5 16.18,-69.87 ; P_CPU_OCP_7_P.5 15.05,-70.99 ; P_CPU_OCP_7_P.5 16.18,-70.99 ; P_CPU_OCP_7_P.5 15.05,-69.87 ; P_CPU_OCP_7_P.2 20.48,-70.99 ; P_CPU_OCP_7_P.2 20.48,-69.87 ; P_CPU_OCP_7_P.2 19.35,-70.99 ; P_CPU_OCP_7_P.2 19.35,-69.87 ; P_BD1_CLK3_N.3 61.9,-11.86 ; P_BD1_CLK3_N.3 60.77,-10.73 ; P_BD1_CLK3_N.3 60.77,-11.86 ; P_BD1_CLK3_N.3 61.9,-10.73 ; P_BD1_TRIG_IN_N.2 89.06,-69.87 ; P_BD1_TRIG_IN_N.2 89.06,-70.99 ; P_BD1_TRIG_IN_N.2 87.93,-70.99 ; P_BD1_TRIG_IN_N.2 87.93,-69.87 ; P_OCP_CPU_5_P.4 73.33,-73.22 ; P_OCP_CPU_5_P.4 73.33,-74.34 ; P_OCP_CPU_5_P.4 72.2,-73.22 ; P_OCP_CPU_5_P.4 72.2,-74.34 ; P_OCP_CPU_6_N.2 61.9,-61.96 ; P_OCP_CPU_6_N.2 60.77,-61.96 ; P_OCP_CPU_6_N.2 61.9,-60.84 ; P_OCP_CPU_6_N.2 60.77,-60.84 ; 60.77,-70.99 P_OCP_CPU_6_P.5 ; P_OCP_CPU_6_P.5 60.77,-69.87 ; P_OCP_CPU_6_P.5 61.9,-69.87 ; P_OCP_CPU_6_P.5 61.9,-70.99
  BOTTOM w0.381: v1(1.94,-36.3) v1(3.43,-36.3) ; P_OCP1.A49 v1(3.43,-58.42) ; v1(1.94,-45.71) v1(3.43,-45.71) ; P_OCP1.A61 v1(3.43,-65.62) ; v1(1.94,-16.9) v1(3.43,-16.9) ; v1(1.94,-42.11) v1(3.43,-42.11) ; P_OCP1.A52 v1(3.43,-60.22) ; P_OCP1.A46 v1(3.43,-56.62) ; v1(1.94,-38.1) v1(3.43,-38.1) ; v1(1.94,-15.1) v1(3.43,-15.1) ; P_OCP1.A58 v1(3.43,-63.82) ; v1(1.94,-34.5) v1(3.43,-34.5) ; P_OCP1.A64 v1(3.43,-67.42) ; v1(1.94,-49.31) v1(3.43,-49.31) ; v1(1.94,-43.91) v1(3.43,-43.91) ; v1(1.94,-29.1) v1(3.43,-29.1) ; P_OCP1.A43 v1(3.43,-54.82) ; v1(1.94,-30.9) v1(3.43,-30.9) ; v1(1.94,-32.7) v1(3.43,-32.7) ; P_OCP1.A67 v1(3.43,-69.22) ; P_OCP1.A55 v1(3.43,-62.02) ; v1(1.94,-47.51) v1(3.43,-47.51)
  vias: v1(1.13,-15.1) v1(1.13,-16.9) v1(1.13,-29.1) v1(1.13,-30.9) v1(1.13,-32.7) v1(1.13,-34.5) v1(1.13,-36.3) v1(1.13,-38.1) v1(1.13,-42.11) v1(1.13,-43.91) v1(1.13,-45.71) v1(1.13,-47.51) v1(1.13,-49.31) v1(5.61,-12.77) v1(6.59,-22.61) v1(6.59,-23.63) v1(6.59,-24.64) v1(12.19,-23.45) v1(12.32,-20.02) v1(12.32,-21.67) v1(13.11,-20.01) v1(83.04,-48.26) v1(83.04,-49.05) v1(96.89,-37.32) v1(96.89,-38.1) v1(98.16,-55.38) v1(99.04,-55.38) v1(99.93,-55.38) v1(100.82,-55.38) v1(101.71,-55.38) v1(102.6,-55.38) v1(103.49,-55.38) v1(104.38,-55.38) v1(110.98,-35.41) v1(110.98,-36.2) v2(17.02,-9.15) v2(17.02,-25.91) v2(17.02,-37.34) v2(17.02,-48.77) v2(17.02,-60.2) v2(17.02,-71.63) v2(17.12,-8.77) v2(17.12,-9.52) v2(17.12,-25.54) v2(17.12,-26.29) v2(17.12,-36.97) v2(17.12,-37.72) v2(17.12,-48.4) v2(17.12,-49.15) v2(17.12,-59.83) v2(17.12,-60.58) v2(17.12,-71.26) v2(17.12,-72.01) v2(17.39,-8.5) v2(17.39,-9.8) v2(17.39,-25.26) v2(17.39,-26.56) v2(17.39,-36.69) v2(17.39,-49.42) v2(17.39,-59.55) v2(17.39,-72.28) v2(17.76,-8.4) v2(17.76,-9.9) v2(17.76,-25.16) v2(17.76,-26.66) v2(17.76,-36.59) v2(17.76,-49.52) v2(17.76,-59.45) v2(17.76,-72.38) v2(18.14,-8.5) v2(18.14,-9.8) v2(18.14,-25.26) v2(18.14,-26.56) v2(18.14,-36.69) v2(18.14,-49.42) v2(18.14,-59.55) v2(18.14,-72.28) v2(18.41,-36.97) v2(18.41,-37.72) v2(18.41,-48.4) v2(18.41,-49.15) v2(18.41,-59.83) v2(18.41,-60.58) v2(18.41,-71.26) v2(18.41,-72.01) v2(18.51,-37.34) v2(18.51,-48.77) v2(18.51,-60.2) v2(18.51,-71.63) v2(28.45,-37.34) v2(28.45,-48.77) v2(28.45,-60.2) v2(28.45,-71.63) v2(28.55,-36.97) v2(28.55,-37.72) v2(28.55,-48.4) v2(28.55,-49.15) v2(28.55,-59.83) v2(28.55,-60.58) v2(28.55,-71.26) v2(28.55,-72.01) v2(28.82,-8.5) v2(28.82,-9.8) v2(28.82,-25.26) v2(28.82,-26.56) v2(28.82,-36.69) v2(28.82,-49.42) v2(28.82,-59.55) v2(28.82,-72.28) v2(29.19,-8.4) v2(29.19,-9.9) v2(29.19,-25.16) v2(29.19,-26.66) v2(29.19,-36.59) v2(29.19,-49.52) v2(29.19,-59.45) v2(29.19,-72.38) v2(29.57,-8.5) v2(29.57,-9.8) v2(29.57,-25.26) v2(29.57,-26.56) v2(29.57,-36.69) v2(29.57,-49.42) v2(29.57,-59.55) v2(29.57,-72.28) v2(29.84,-8.77) v2(29.84,-9.52) v2(29.84,-25.54) v2(29.84,-26.29) v2(29.84,-36.97) v2(29.84,-37.72) v2(29.84,-48.4) v2(29.84,-49.15) v2(29.84,-59.83) v2(29.84,-60.58) v2(29.84,-71.26) v2(29.84,-72.01) v2(29.94,-9.15) v2(29.94,-25.91) v2(29.94,-37.34) v2(29.94,-48.77) v2(29.94,-60.2) v2(29.94,-71.63) v2(39.88,-9.15) v2(39.88,-25.91) v2(39.88,-37.34) v2(39.88,-48.77) v2(39.88,-60.2) v2(39.88,-71.63) v2(39.98,-8.77) v2(39.98,-9.52) v2(39.98,-25.54) v2(39.98,-26.29) v2(39.98,-36.97) v2(39.98,-37.72) v2(39.98,-48.4) v2(39.98,-49.15) v2(39.98,-59.83) v2(39.98,-60.58) v2(39.98,-71.26) v2(39.98,-72.01) v2(40.25,-8.5) v2(40.25,-9.8) v2(40.25,-25.26) v2(40.25,-26.56) v2(40.25,-36.69) v2(40.25,-49.42) v2(40.25,-59.55) v2(40.25,-72.28) v2(40.62,-8.4) v2(40.62,-9.9) v2(40.62,-25.16) v2(40.62,-26.66) v2(40.62,-36.59) v2(40.62,-49.52) v2(40.62,-59.45) v2(40.62,-72.38) v2(41,-8.5) v2(41,-9.8) v2(41,-25.26) v2(41,-26.56) v2(41,-36.69) v2(41,-49.42) v2(41,-59.55) v2(41,-72.28) v2(41.27,-36.97) v2(41.27,-37.72) v2(41.27,-48.4) v2(41.27,-49.15) v2(41.27,-59.83) v2(41.27,-60.58) v2(41.27,-71.26) v2(41.27,-72.01) v2(41.37,-37.34) v2(41.37,-48.77) v2(41.37,-60.2) v2(41.37,-71.63) v2(51.68,-8.5) v2(51.68,-9.8) v2(51.68,-25.26) v2(51.68,-26.56) v2(52.05,-8.4) v2(52.05,-9.9) v2(52.05,-25.16) v2(52.05,-26.66) v2(52.43,-8.5) v2(52.43,-9.8) v2(52.43,-25.26) v2(52.43,-26.56) v2(52.7,-8.77) v2(52.7,-9.52) v2(52.7,-25.54) v2(52.7,-26.29) v2(52.8,-9.15) v2(52.8,-25.91) v2(85.6,-60.2) v2(85.6,-71.63) v2(85.7,-59.83) v2(85.7,-60.58) v2(85.7,-71.26) v2(85.7,-72.01) v2(85.97,-59.55) v2(85.97,-72.28) v2(86.34,-59.45) v2(86.34,-72.38) v2(86.72,-59.55) v2(86.72,-72.28) v2(86.99,-59.83) v2(86.99,-60.58) v2(86.99,-71.26) v2(86.99,-72.01) v2(87.09,-60.2) v2(87.09,-71.63) v2(98.3,-60.2) v2(98.3,-71.63) v2(98.4,-59.83) v2(98.4,-60.58) v2(98.4,-71.26) v2(98.4,-72.01) v2(98.67,-59.55) v2(98.67,-72.28) v2(99.04,-59.45) v2(99.04,-72.38) v2(99.42,-59.55) v2(99.42,-72.28) v2(99.69,-59.83) v2(99.69,-60.58) v2(99.69,-71.26) v2(99.69,-72.01) v2(99.79,-60.2) v2(99.79,-71.63) v3(51.36,-37.34) v3(51.36,-48.77) v3(51.36,-60.2) v3(51.36,-71.63) v3(51.45,-36.99) v3(51.45,-37.69) v3(51.45,-48.42) v3(51.45,-49.12) v3(51.45,-59.85) v3(51.45,-60.55) v3(51.45,-71.28) v3(51.45,-71.98) v3(51.71,-36.74) v3(51.71,-49.38) v3(51.71,-59.6) v3(51.71,-72.24) v3(52.05,-36.64) v3(52.05,-49.47) v3(52.05,-59.5) v3(52.05,-72.33) v3(52.4,-36.74) v3(52.4,-49.38) v3(52.4,-59.6) v3(52.4,-72.24) v3(52.66,-36.99) v3(52.66,-37.69) v3(52.66,-48.42) v3(52.66,-49.12) v3(52.66,-59.85) v3(52.66,-60.55) v3(52.66,-71.28) v3(52.66,-71.98) v3(52.75,-37.34) v3(52.75,-48.77) v3(52.75,-60.2) v3(52.75,-71.63) v3(62.79,-9.15) v3(62.79,-25.91) v3(62.79,-37.34) v3(62.79,-48.77) v3(62.79,-60.2) v3(62.79,-71.63) v3(62.88,-8.8) v3(62.88,-9.5) v3(62.88,-25.56) v3(62.88,-26.26) v3(62.88,-36.99) v3(62.88,-37.69) v3(62.88,-48.42) v3(62.88,-49.12) v3(62.88,-59.85) v3(62.88,-60.55) v3(62.88,-71.28) v3(62.88,-71.98) v3(63.14,-8.54) v3(63.14,-9.75) v3(63.14,-25.31) v3(63.14,-26.52) v3(63.14,-36.74) v3(63.14,-49.38) v3(63.14,-59.6) v3(63.14,-72.24) v3(63.48,-8.45) v3(63.48,-9.85) v3(63.48,-25.21) v3(63.48,-26.61) v3(63.48,-36.64) v3(63.48,-49.47) v3(63.48,-59.5) v3(63.48,-72.33) v3(63.83,-8.54) v3(63.83,-9.75) v3(63.83,-25.31) v3(63.83,-26.52) v3(63.83,-36.74) v3(63.83,-49.38) v3(63.83,-59.6) v3(63.83,-72.24) v3(64.09,-36.99) v3(64.09,-37.69) v3(64.09,-48.42) v3(64.09,-49.12) v3(64.09,-59.85) v3(64.09,-60.55) v3(64.09,-71.28) v3(64.09,-71.98) v3(64.18,-37.34) v3(64.18,-48.77) v3(64.18,-60.2) v3(64.18,-71.63) v3(74.22,-37.34) v3(74.22,-48.77) v3(74.22,-60.2) v3(74.22,-71.63) v3(74.31,-36.99) v3(74.31,-37.69) v3(74.31,-48.42) v3(74.31,-49.12) v3(74.31,-59.85) v3(74.31,-60.55) v3(74.31,-71.28) v3(74.31,-71.98) v3(74.57,-8.54) v3(74.57,-9.75) v3(74.57,-25.31) v3(74.57,-26.52) v3(74.57,-36.74) v3(74.57,-49.38) v3(74.57,-59.6) v3(74.57,-72.24) v3(74.91,-8.45) v3(74.91,-9.85) v3(74.91,-25.21) v3(74.91,-26.61) v3(74.91,-36.64) v3(74.91,-49.47) v3(74.91,-59.5) v3(74.91,-72.33) v3(75.26,-8.54) v3(75.26,-9.75) v3(75.26,-25.31) v3(75.26,-26.52) v3(75.26,-36.74) v3(75.26,-49.38) v3(75.26,-59.6) v3(75.26,-72.24) v3(75.52,-8.8) v3(75.52,-9.5) v3(75.52,-25.56) v3(75.52,-26.26) v3(75.52,-36.99) v3(75.52,-37.69) v3(75.52,-48.42) v3(75.52,-49.12) v3(75.52,-59.85) v3(75.52,-60.55) v3(75.52,-71.28) v3(75.52,-71.98) v3(75.61,-9.15) v3(75.61,-25.91) v3(75.61,-37.34) v3(75.61,-48.77) v3(75.61,-60.2) v3(75.61,-71.63) v3(85.65,-9.15) v3(85.65,-20.58) v3(85.74,-8.8) v3(85.74,-9.5) v3(85.74,-20.23) v3(85.74,-20.93) v3(86,-8.54) v3(86,-9.75) v3(86,-19.97) v3(86,-21.18) v3(86.34,-8.45) v3(86.34,-9.85) v3(86.34,-19.88) v3(86.34,-21.28) v3(86.69,-8.54) v3(86.69,-9.75) v3(86.69,-19.97) v3(86.69,-21.18) v3(97.43,-8.54) v3(97.43,-9.75) v3(97.43,-19.97) v3(97.43,-21.18) v3(97.77,-8.45) v3(97.77,-9.85) v3(97.77,-19.88) v3(97.77,-21.28) v3(98.12,-8.54) v3(98.12,-9.75) v3(98.12,-19.97) v3(98.12,-21.18) v3(98.38,-8.8) v3(98.38,-9.5) v3(98.38,-20.23) v3(98.38,-20.93) v3(98.47,-9.15) v3(98.47,-20.58) v4(106.67,-7.86) v4(106.67,-72.86) v4(107.58,-5.68) v4(107.58,-10.04) v4(107.58,-70.68) v4(107.58,-75.04) v4(109.76,-4.78) v4(109.76,-10.95) v4(109.76,-69.78) v4(109.76,-75.95) v4(111.94,-5.68) v4(111.94,-10.04) v4(111.94,-70.68) v4(111.94,-75.04) v5(92.95,-65.92)
